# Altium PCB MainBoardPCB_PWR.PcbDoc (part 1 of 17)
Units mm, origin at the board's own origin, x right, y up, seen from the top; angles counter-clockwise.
Board outline 333.63 x 349.38 mm, 16 copper layers (L1, L2 (GND), L3 (Sign), L4 (GND), L5 (Sign), L6 (PWR/GND), L7(PWR/GND), L8 (PWR/GND), L9 (PWR/GND), L10 (PWR/GND), L11 (PWR/GND), L12 (Sign), L13 (GND), L14 (Sign), L15 (GND), L16), stack 2.503 mm thick; 2187 components, 1615 nets, 7987 pads, 1695 vias.
Unrouted connection lines stored in the file: 4757.
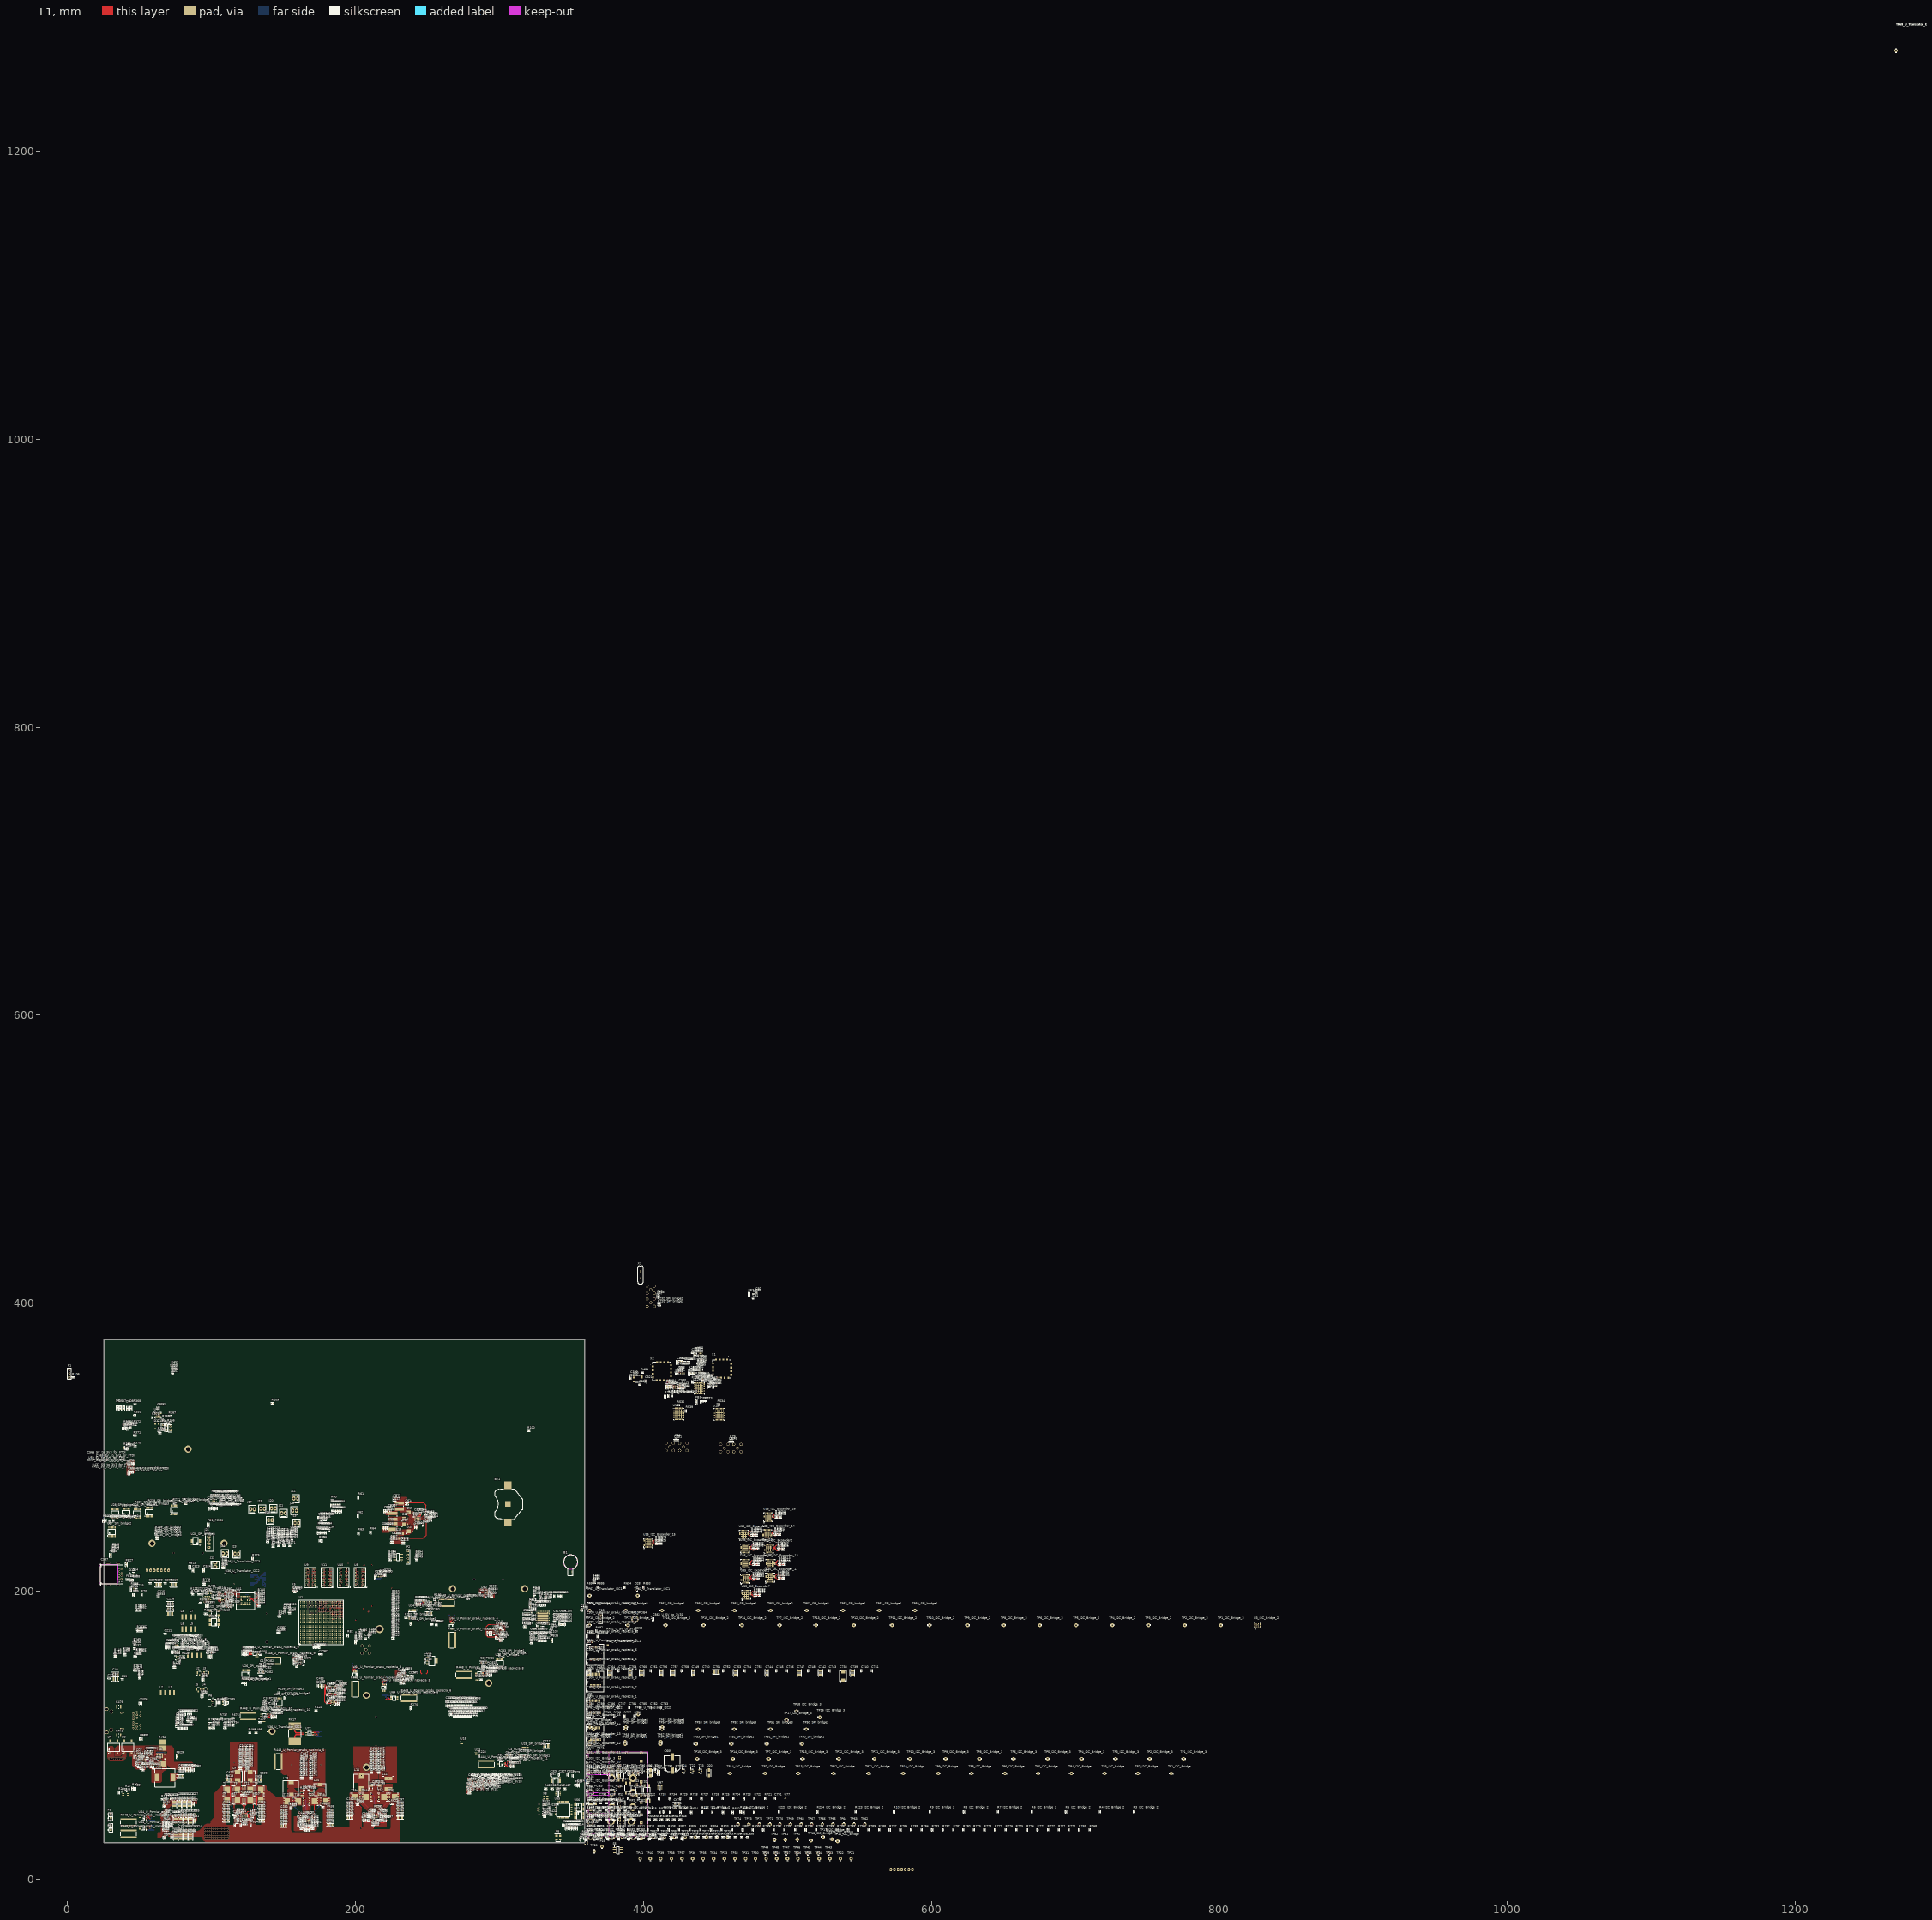
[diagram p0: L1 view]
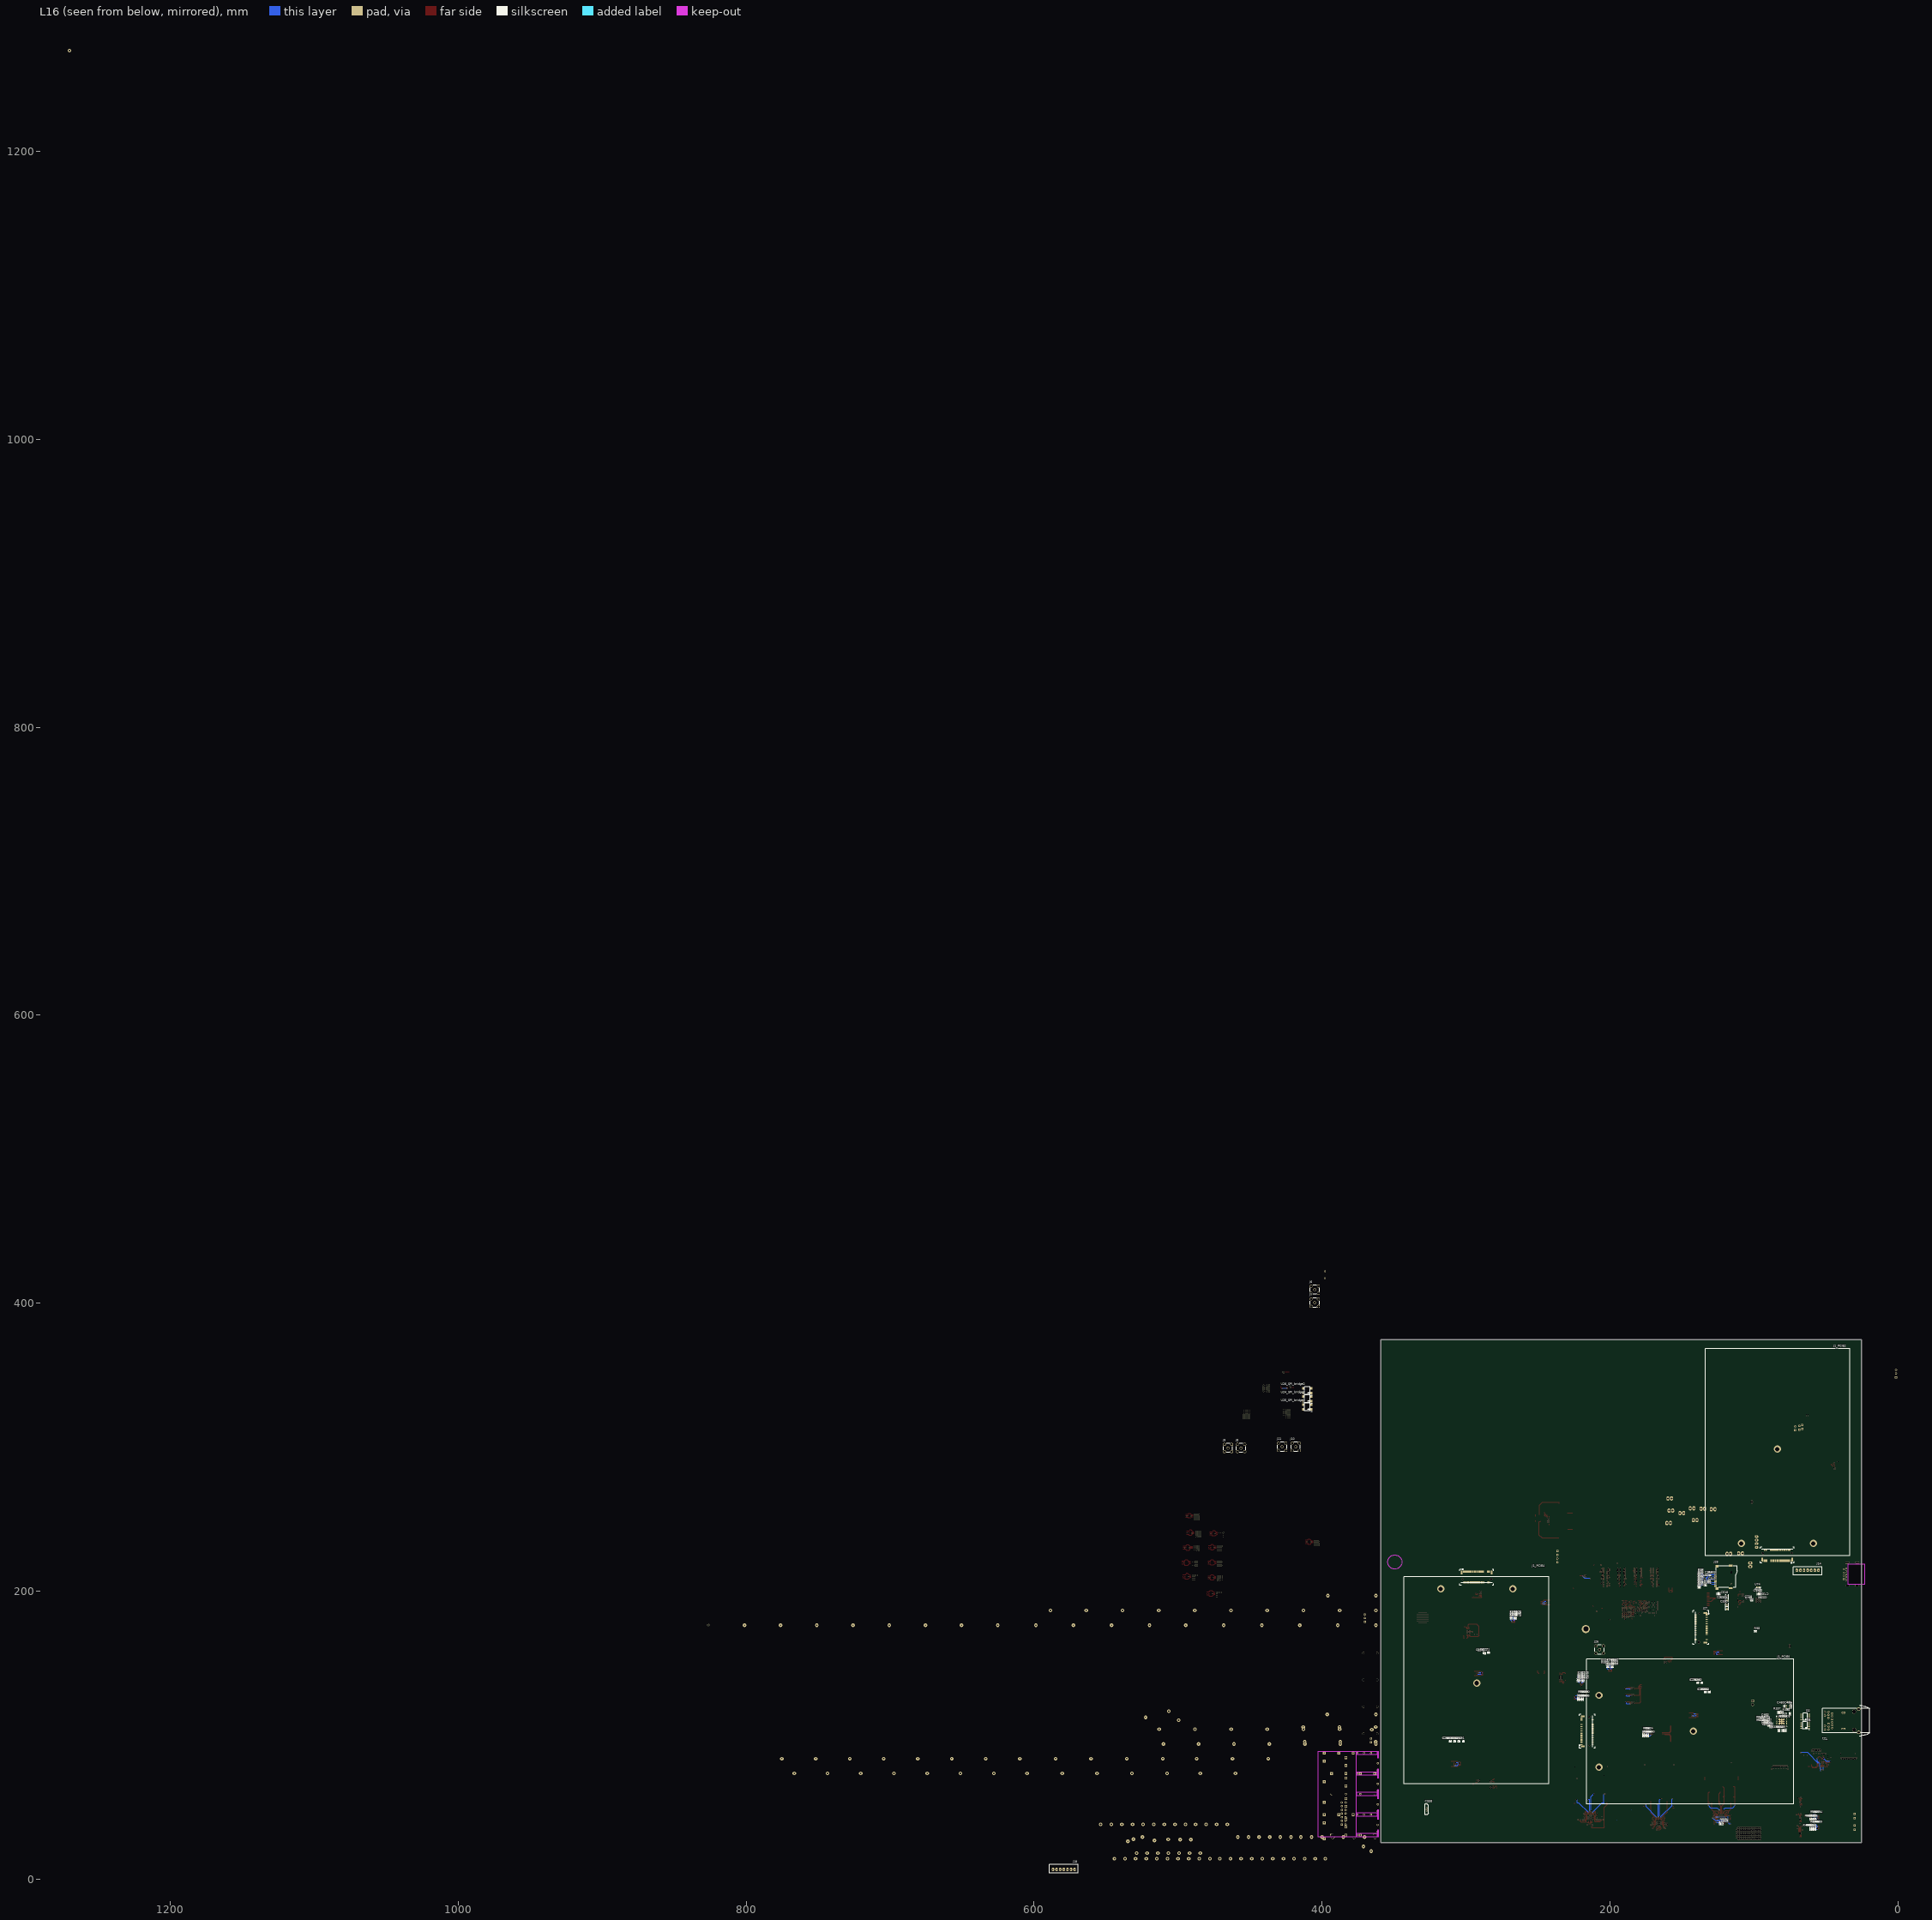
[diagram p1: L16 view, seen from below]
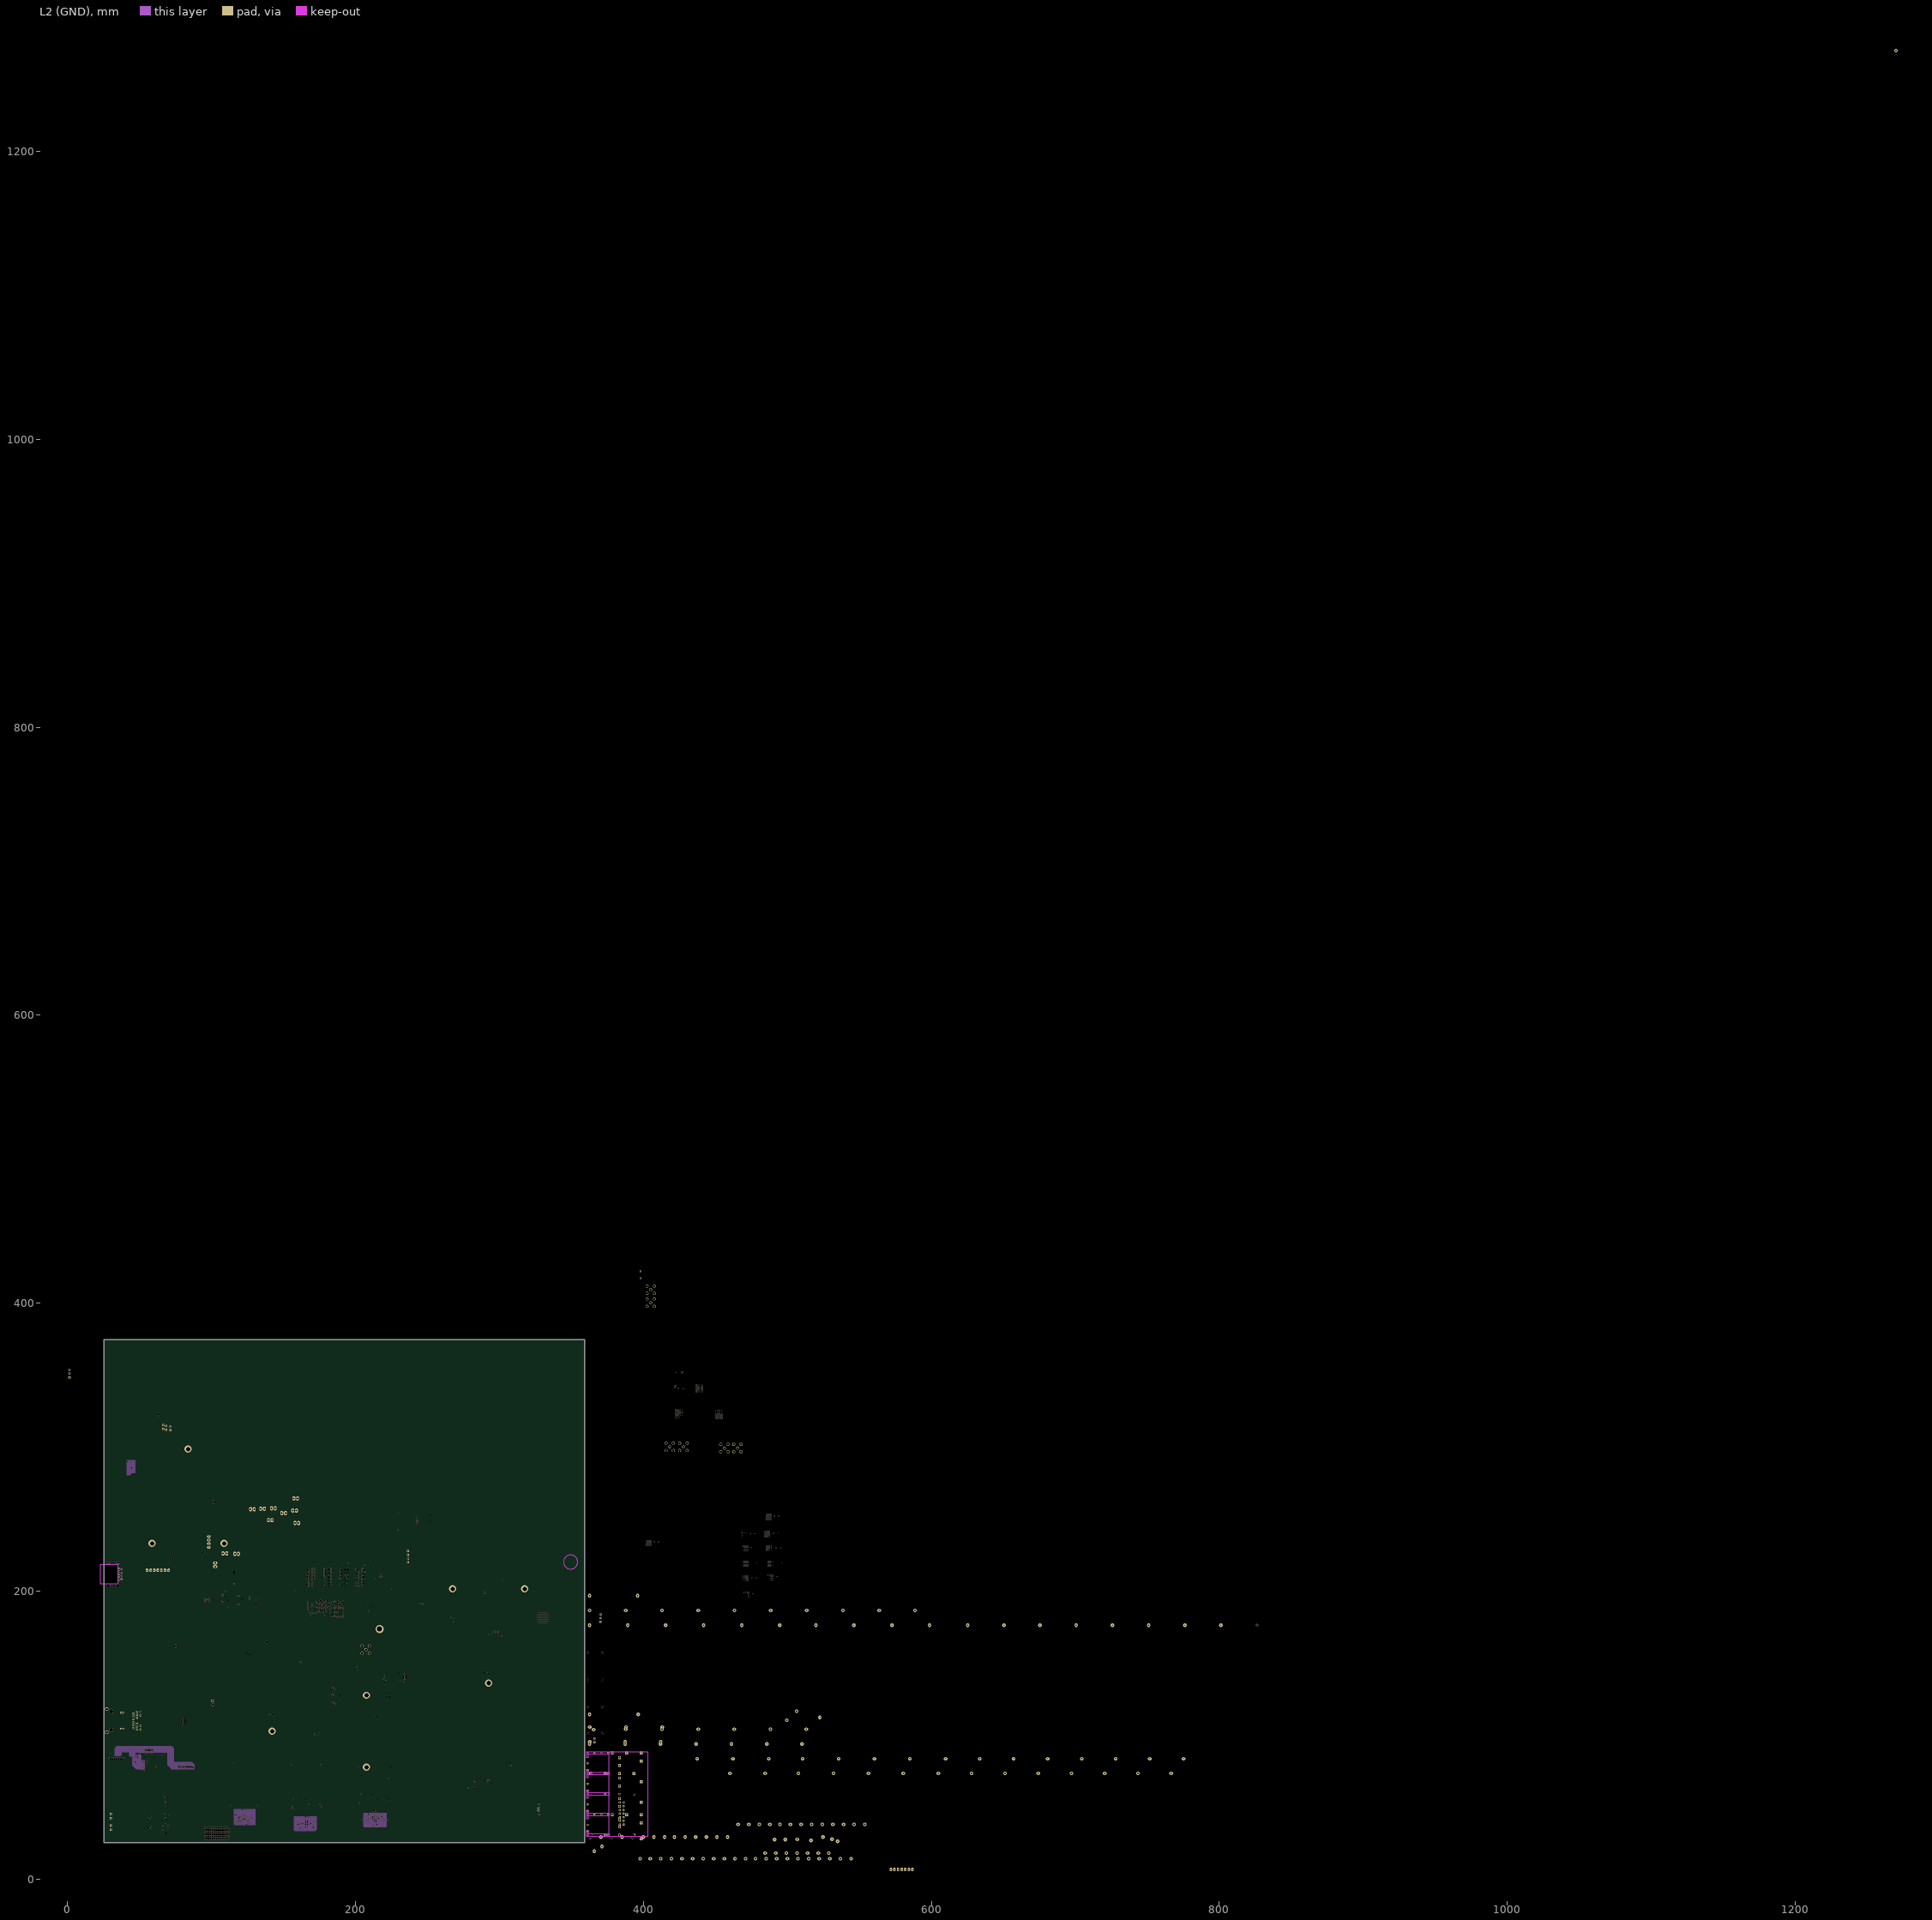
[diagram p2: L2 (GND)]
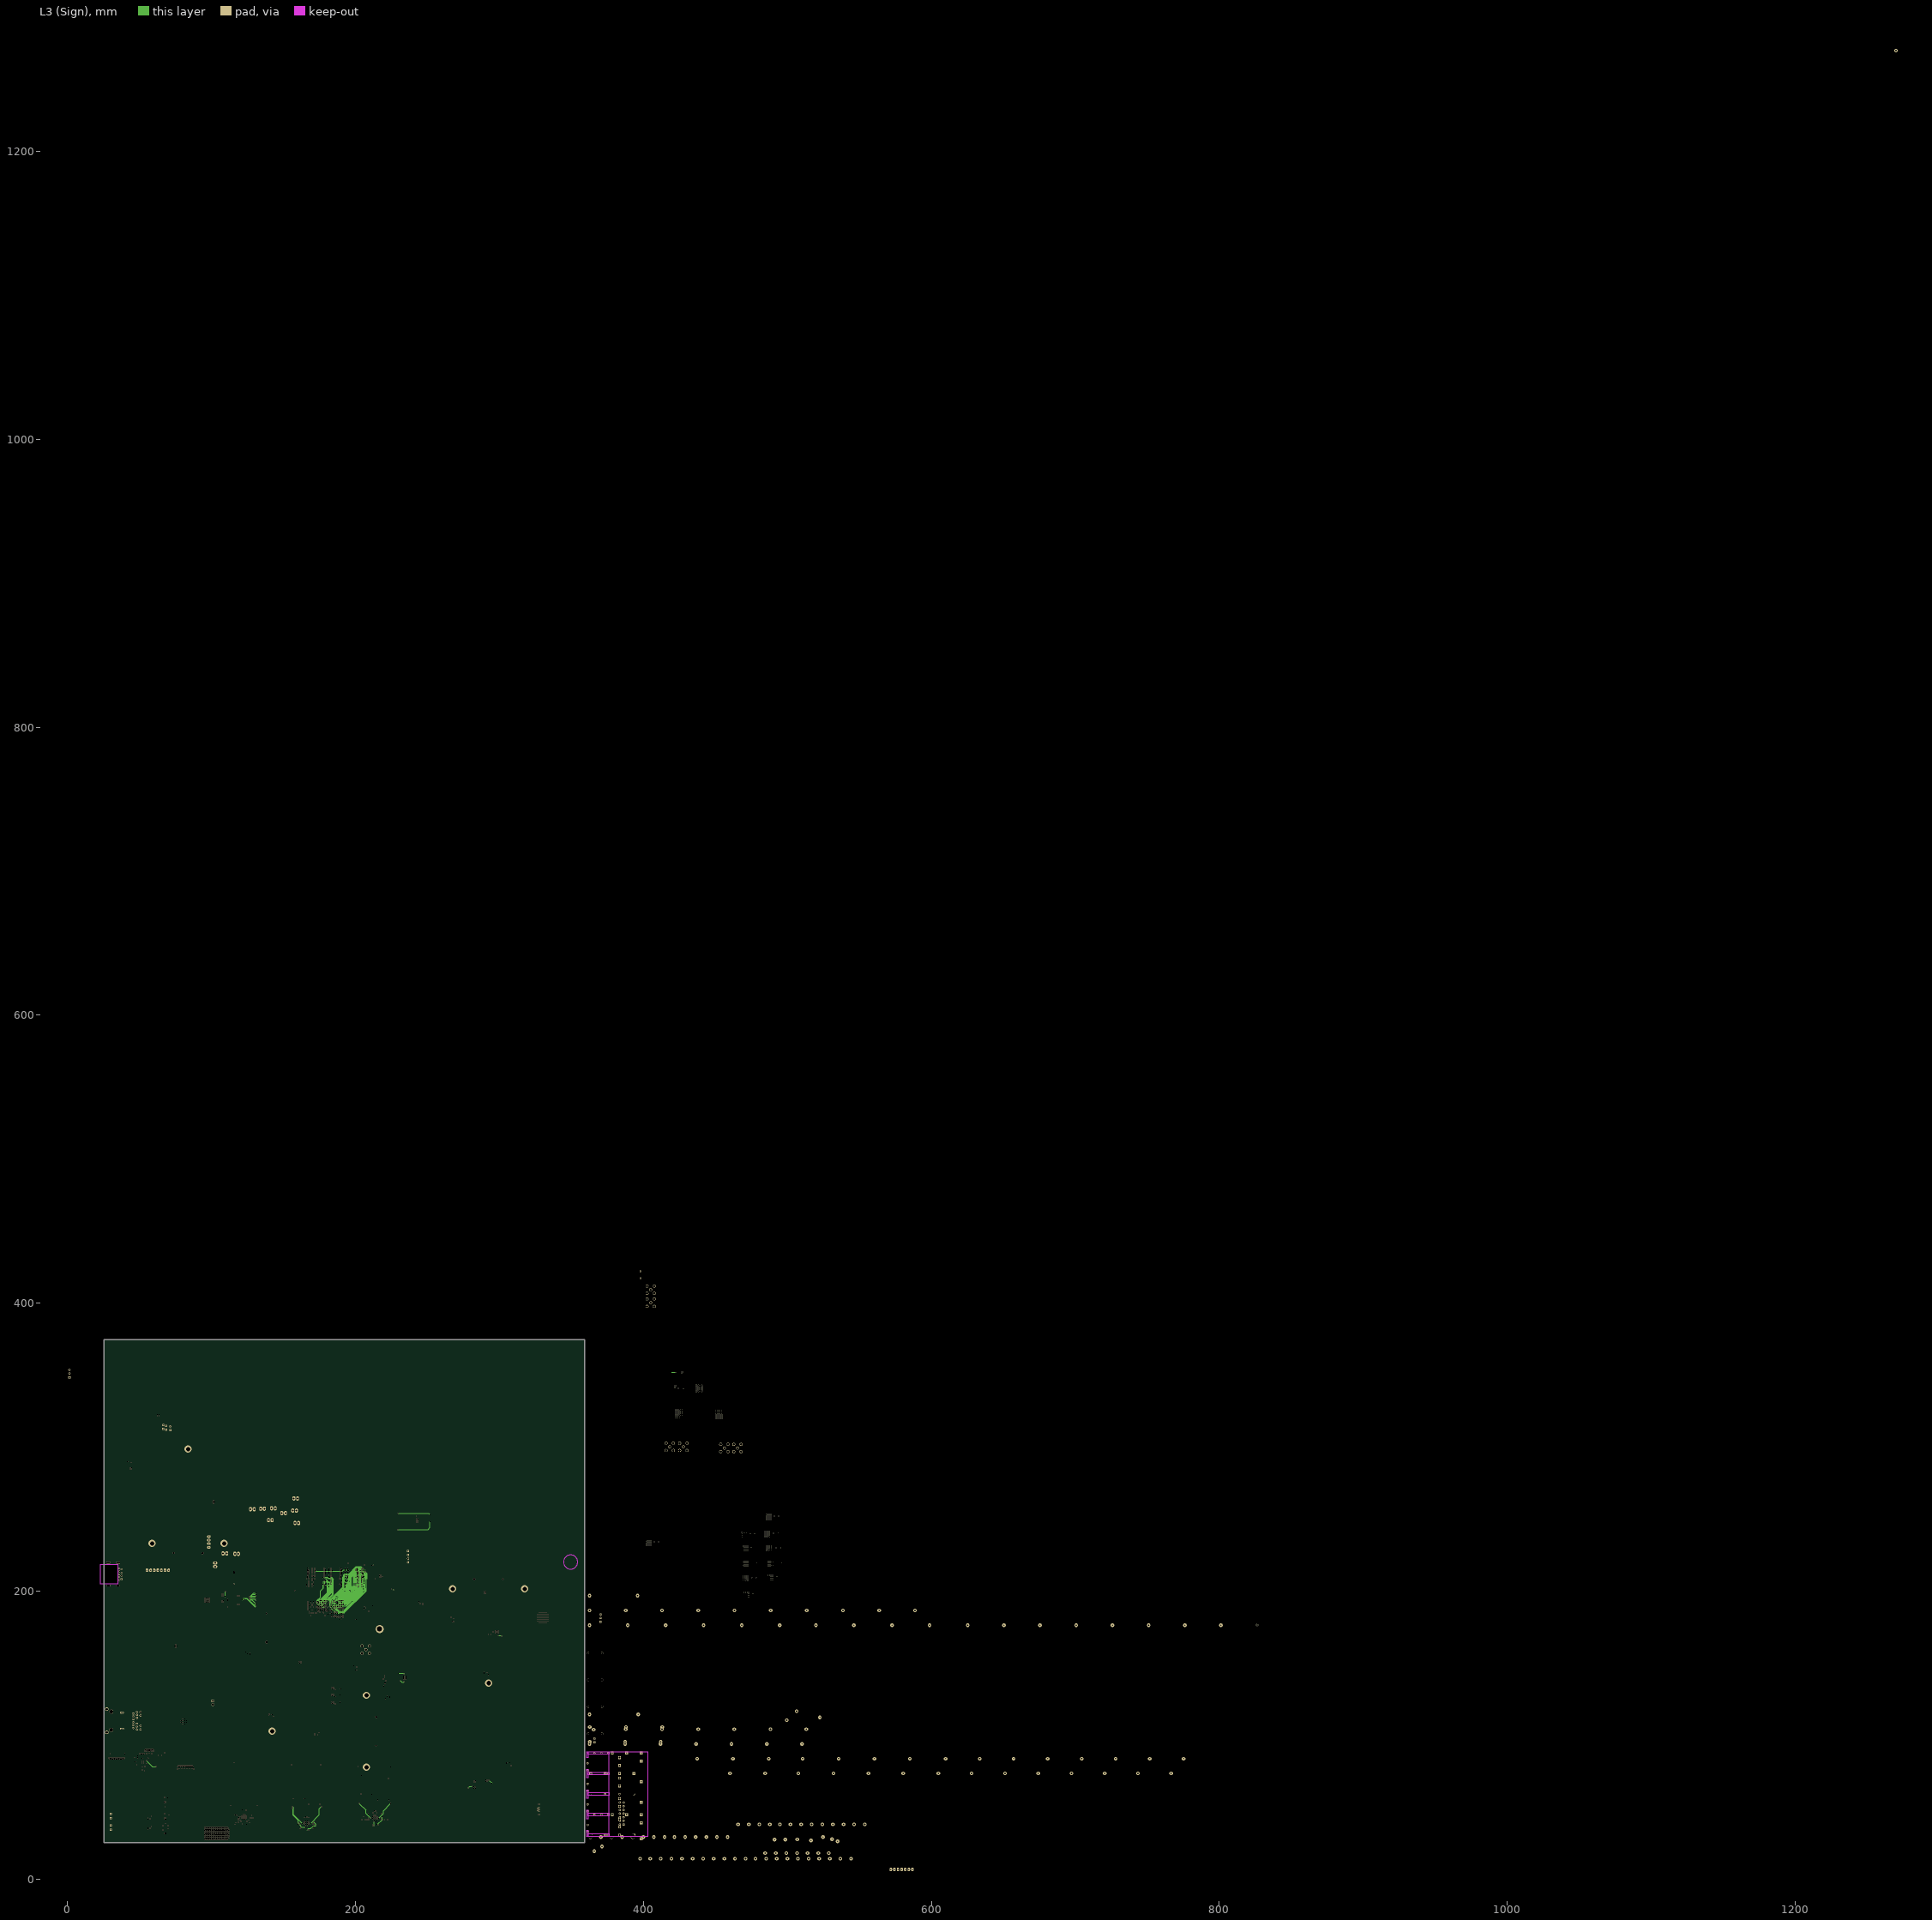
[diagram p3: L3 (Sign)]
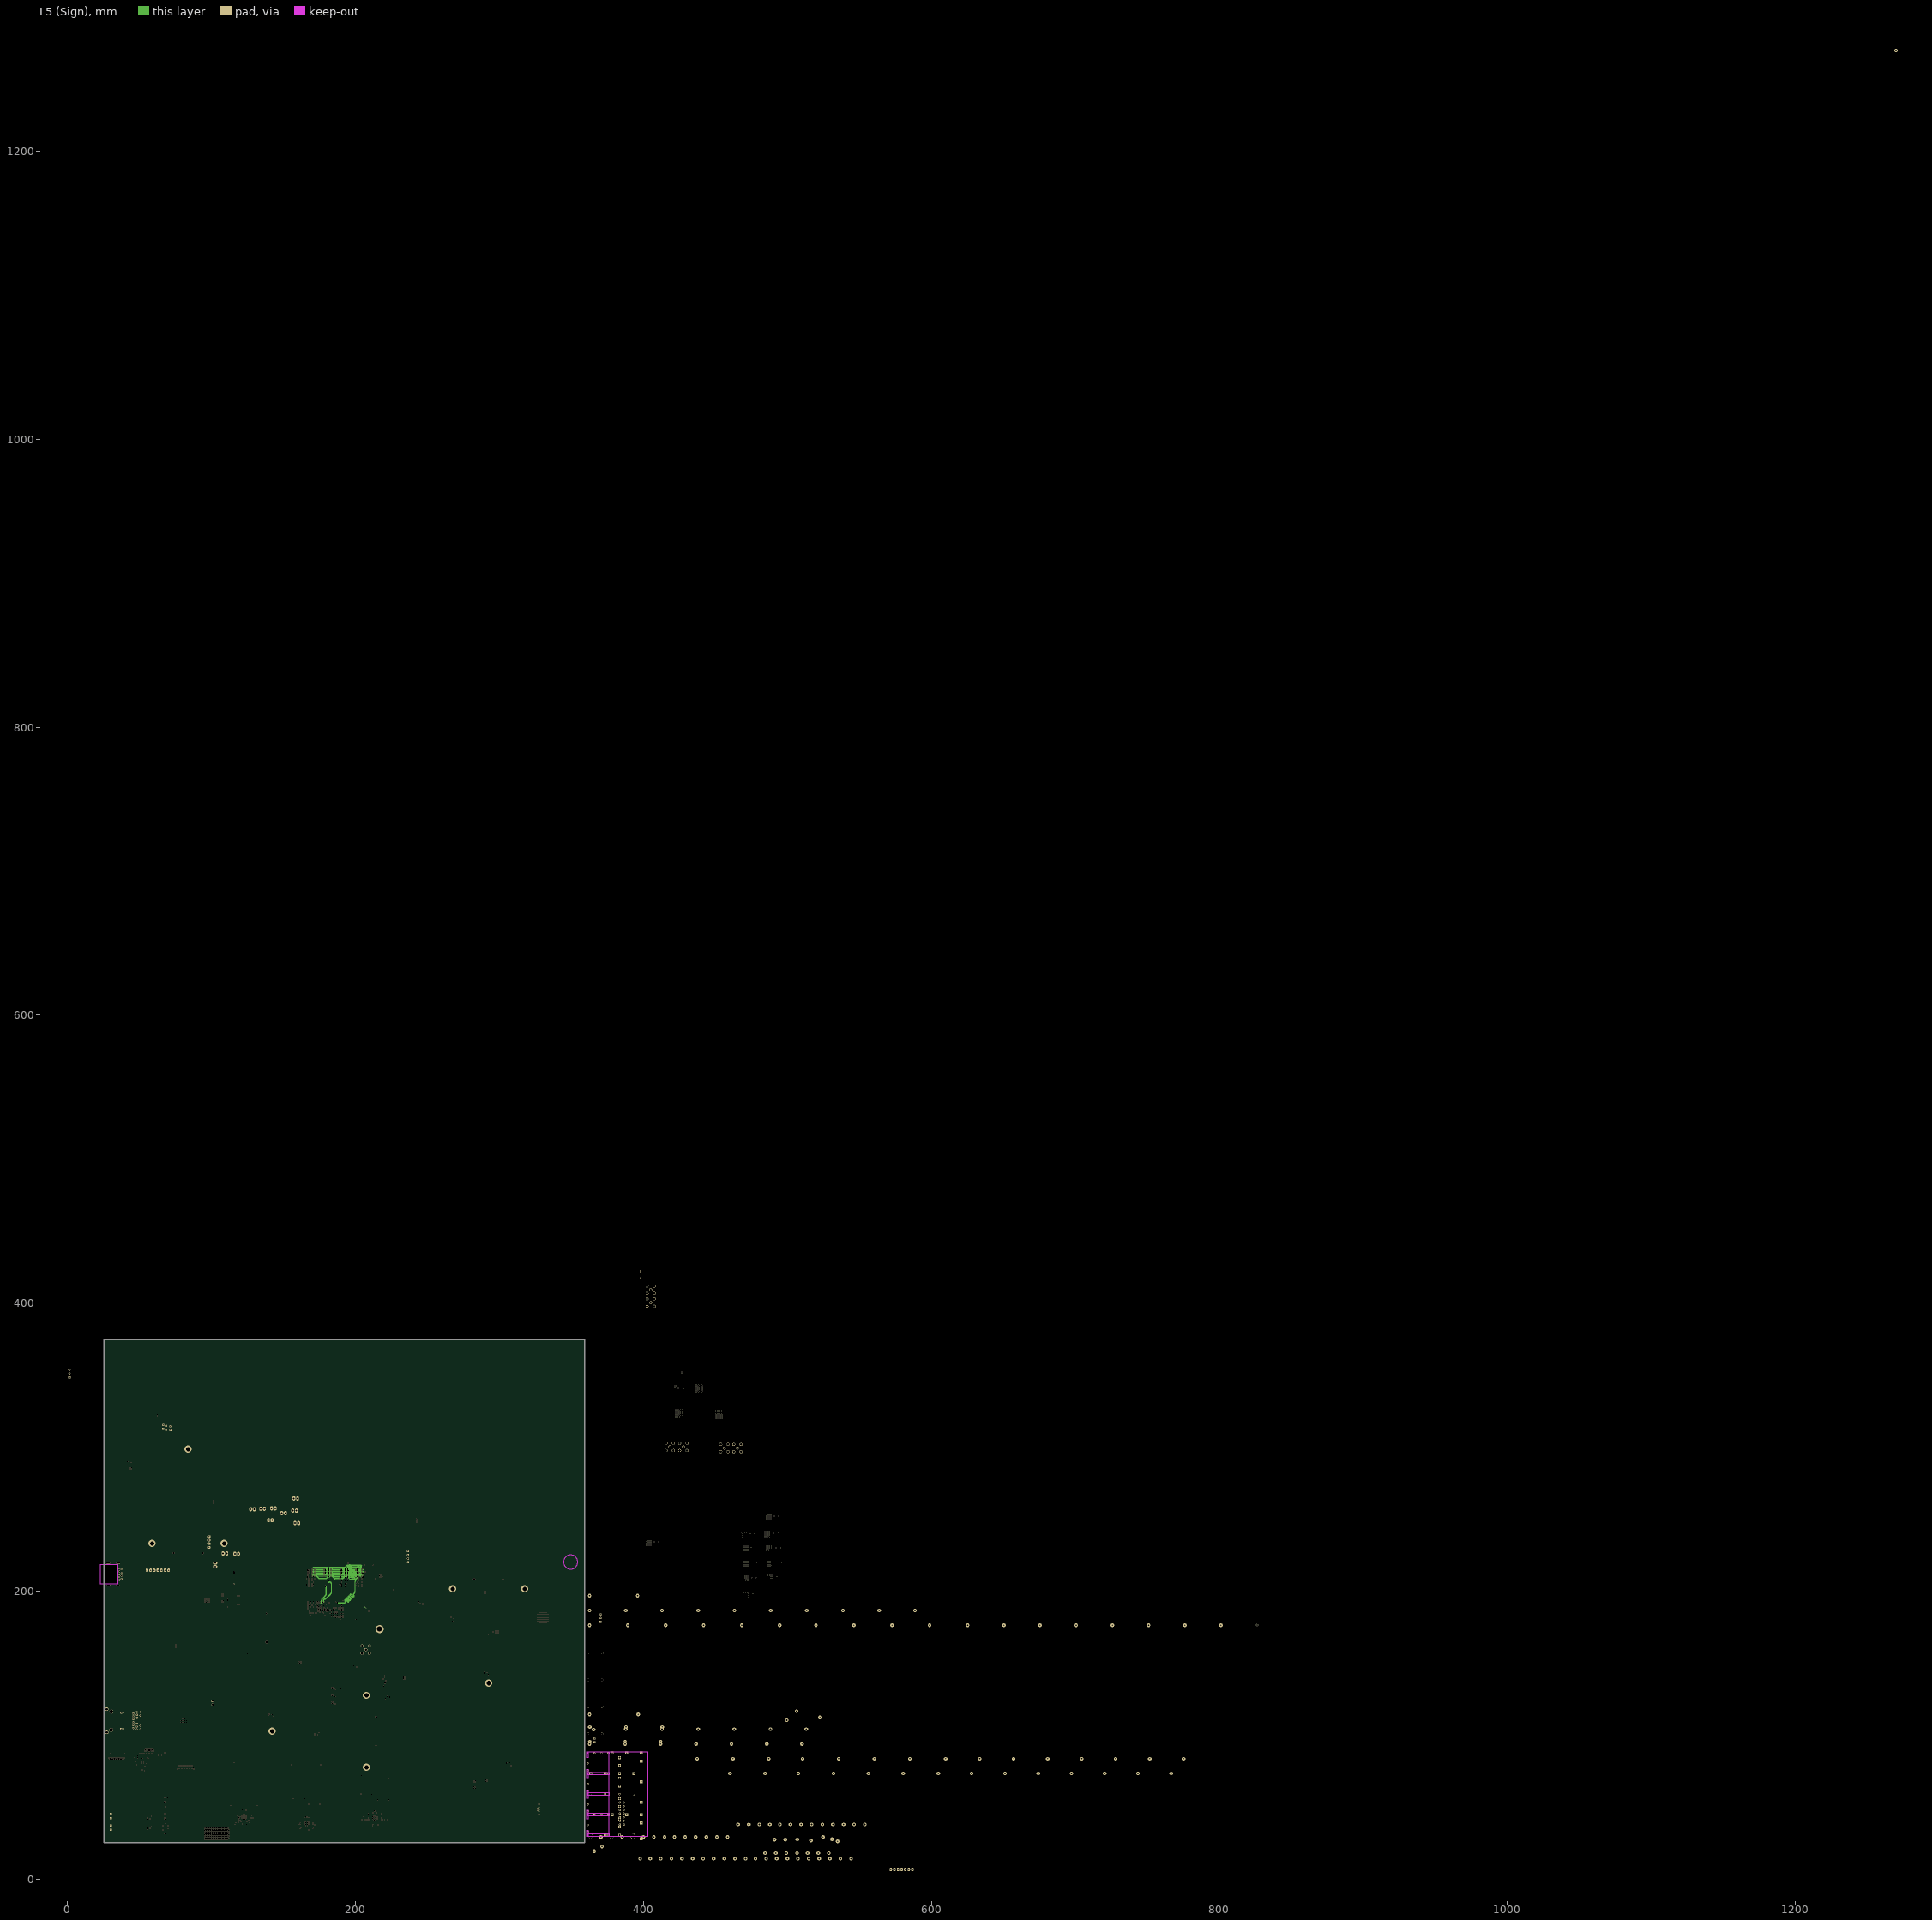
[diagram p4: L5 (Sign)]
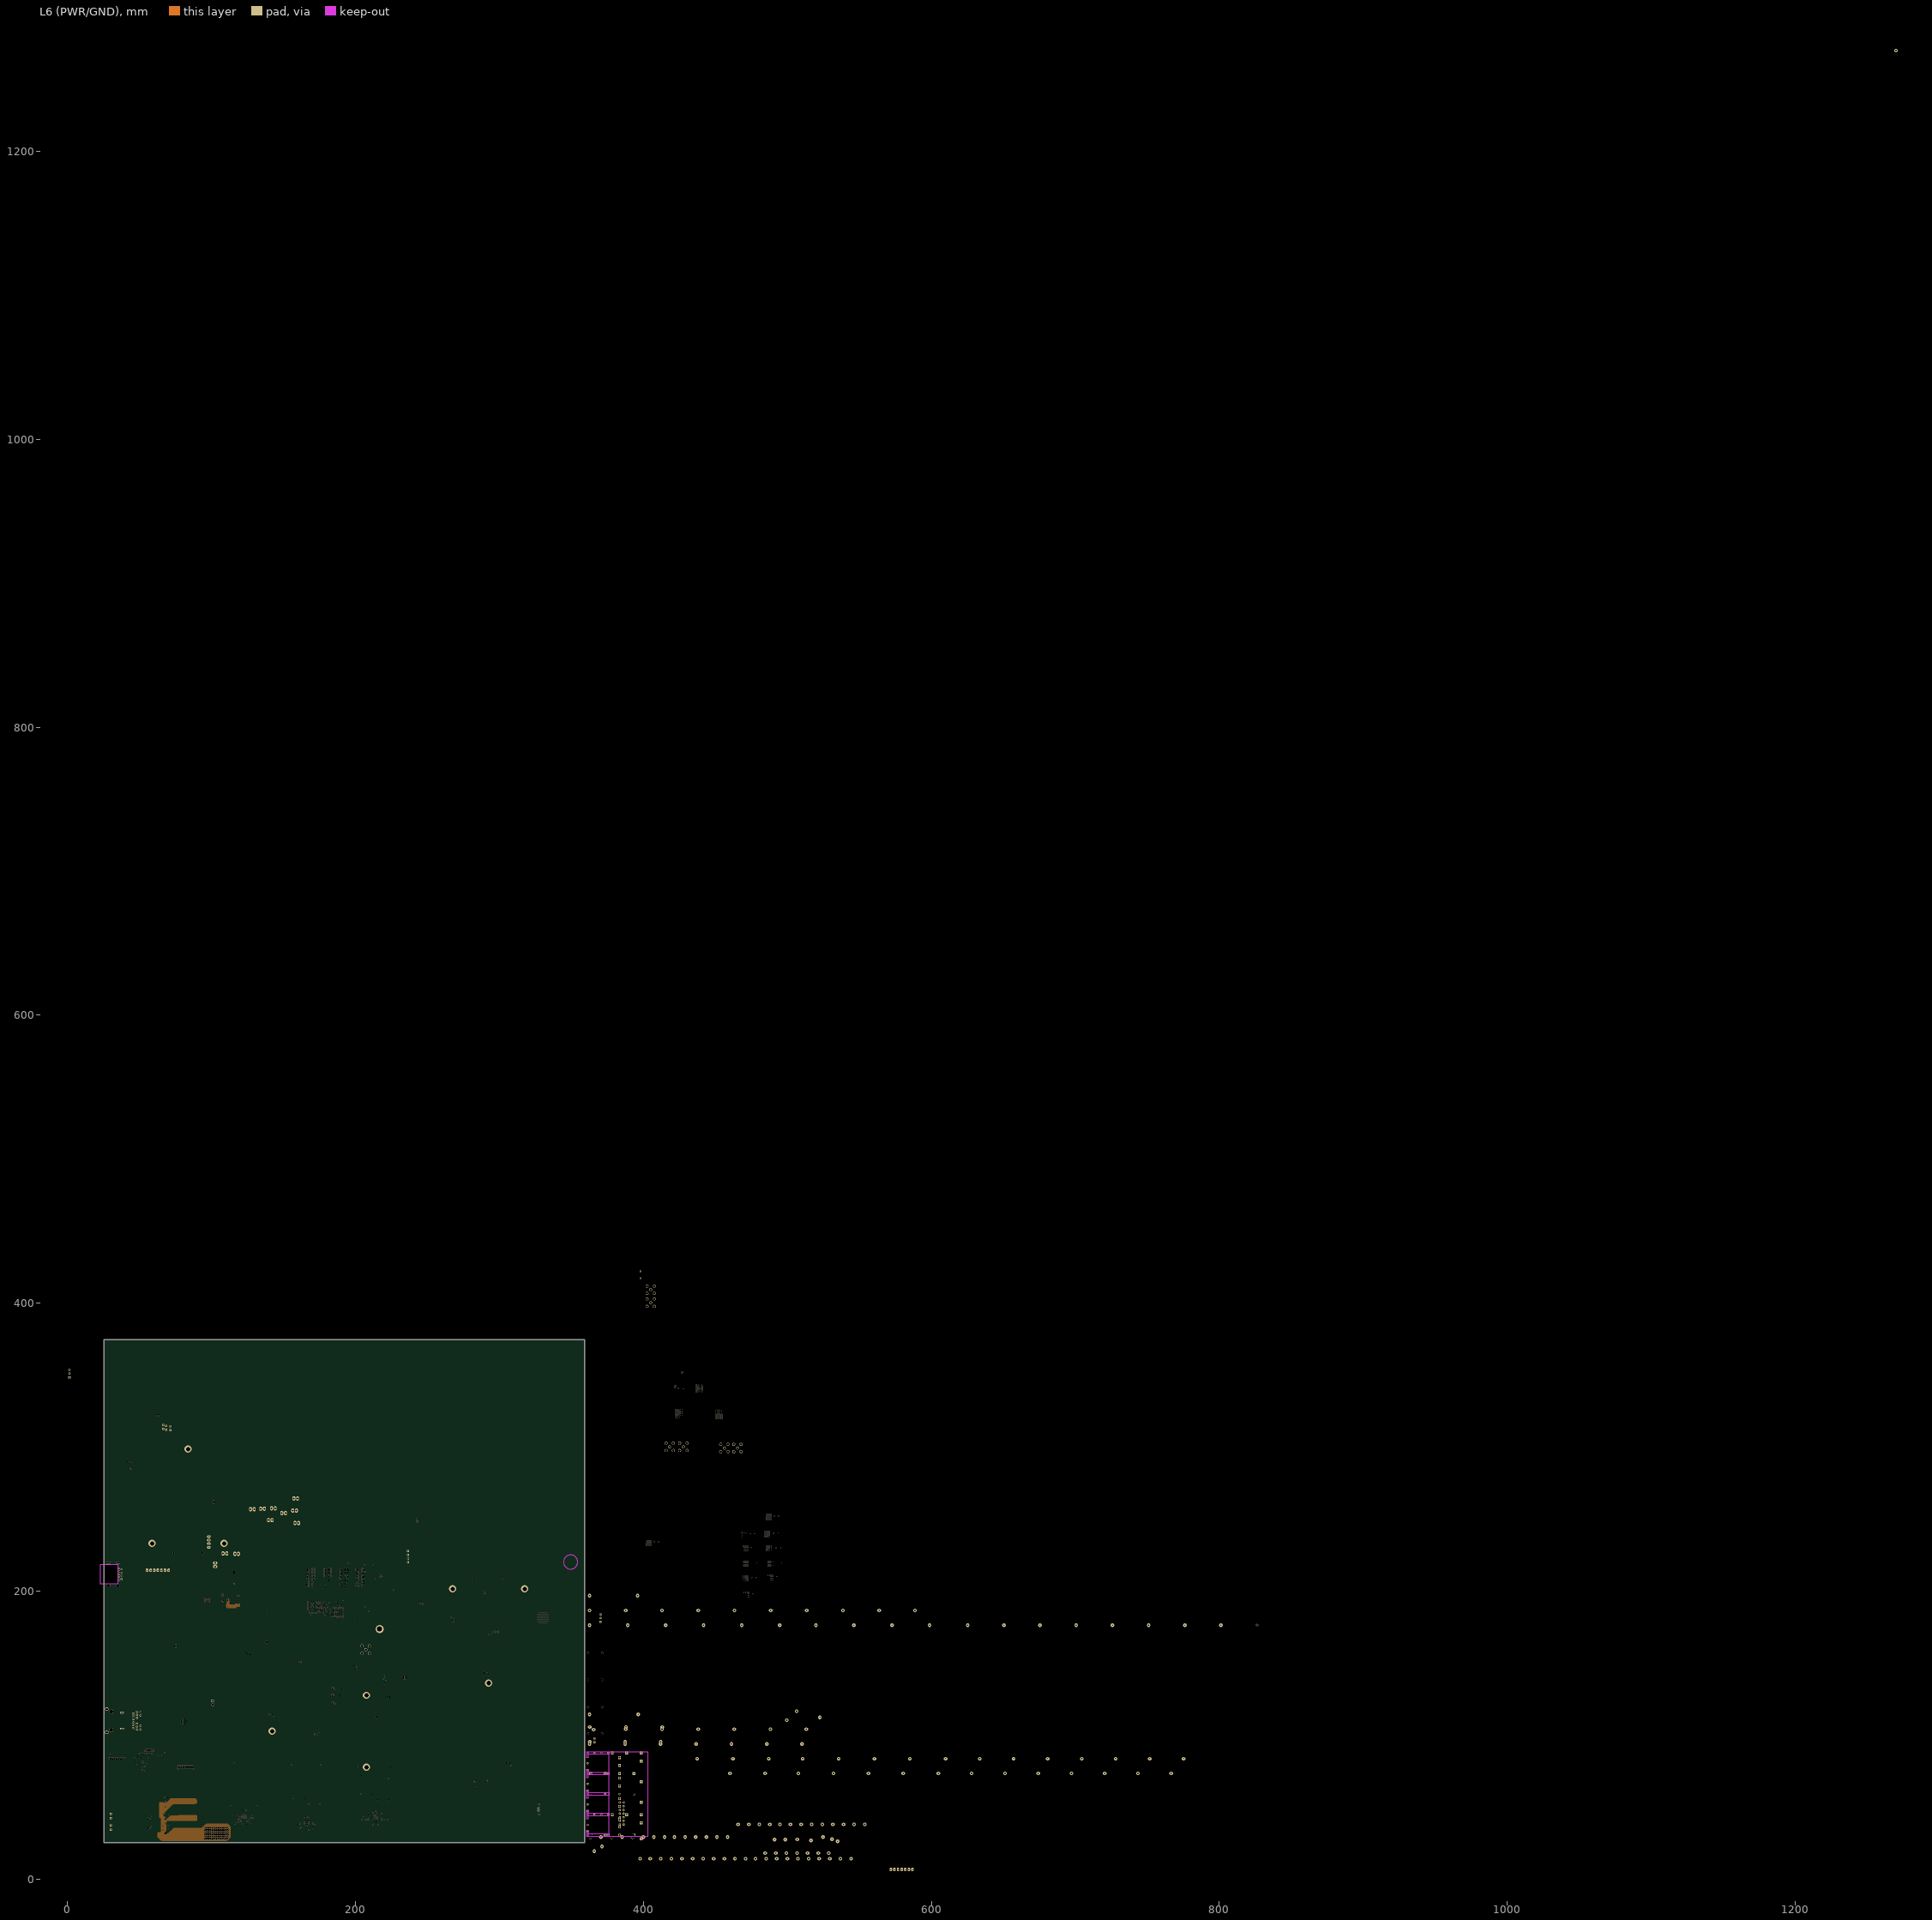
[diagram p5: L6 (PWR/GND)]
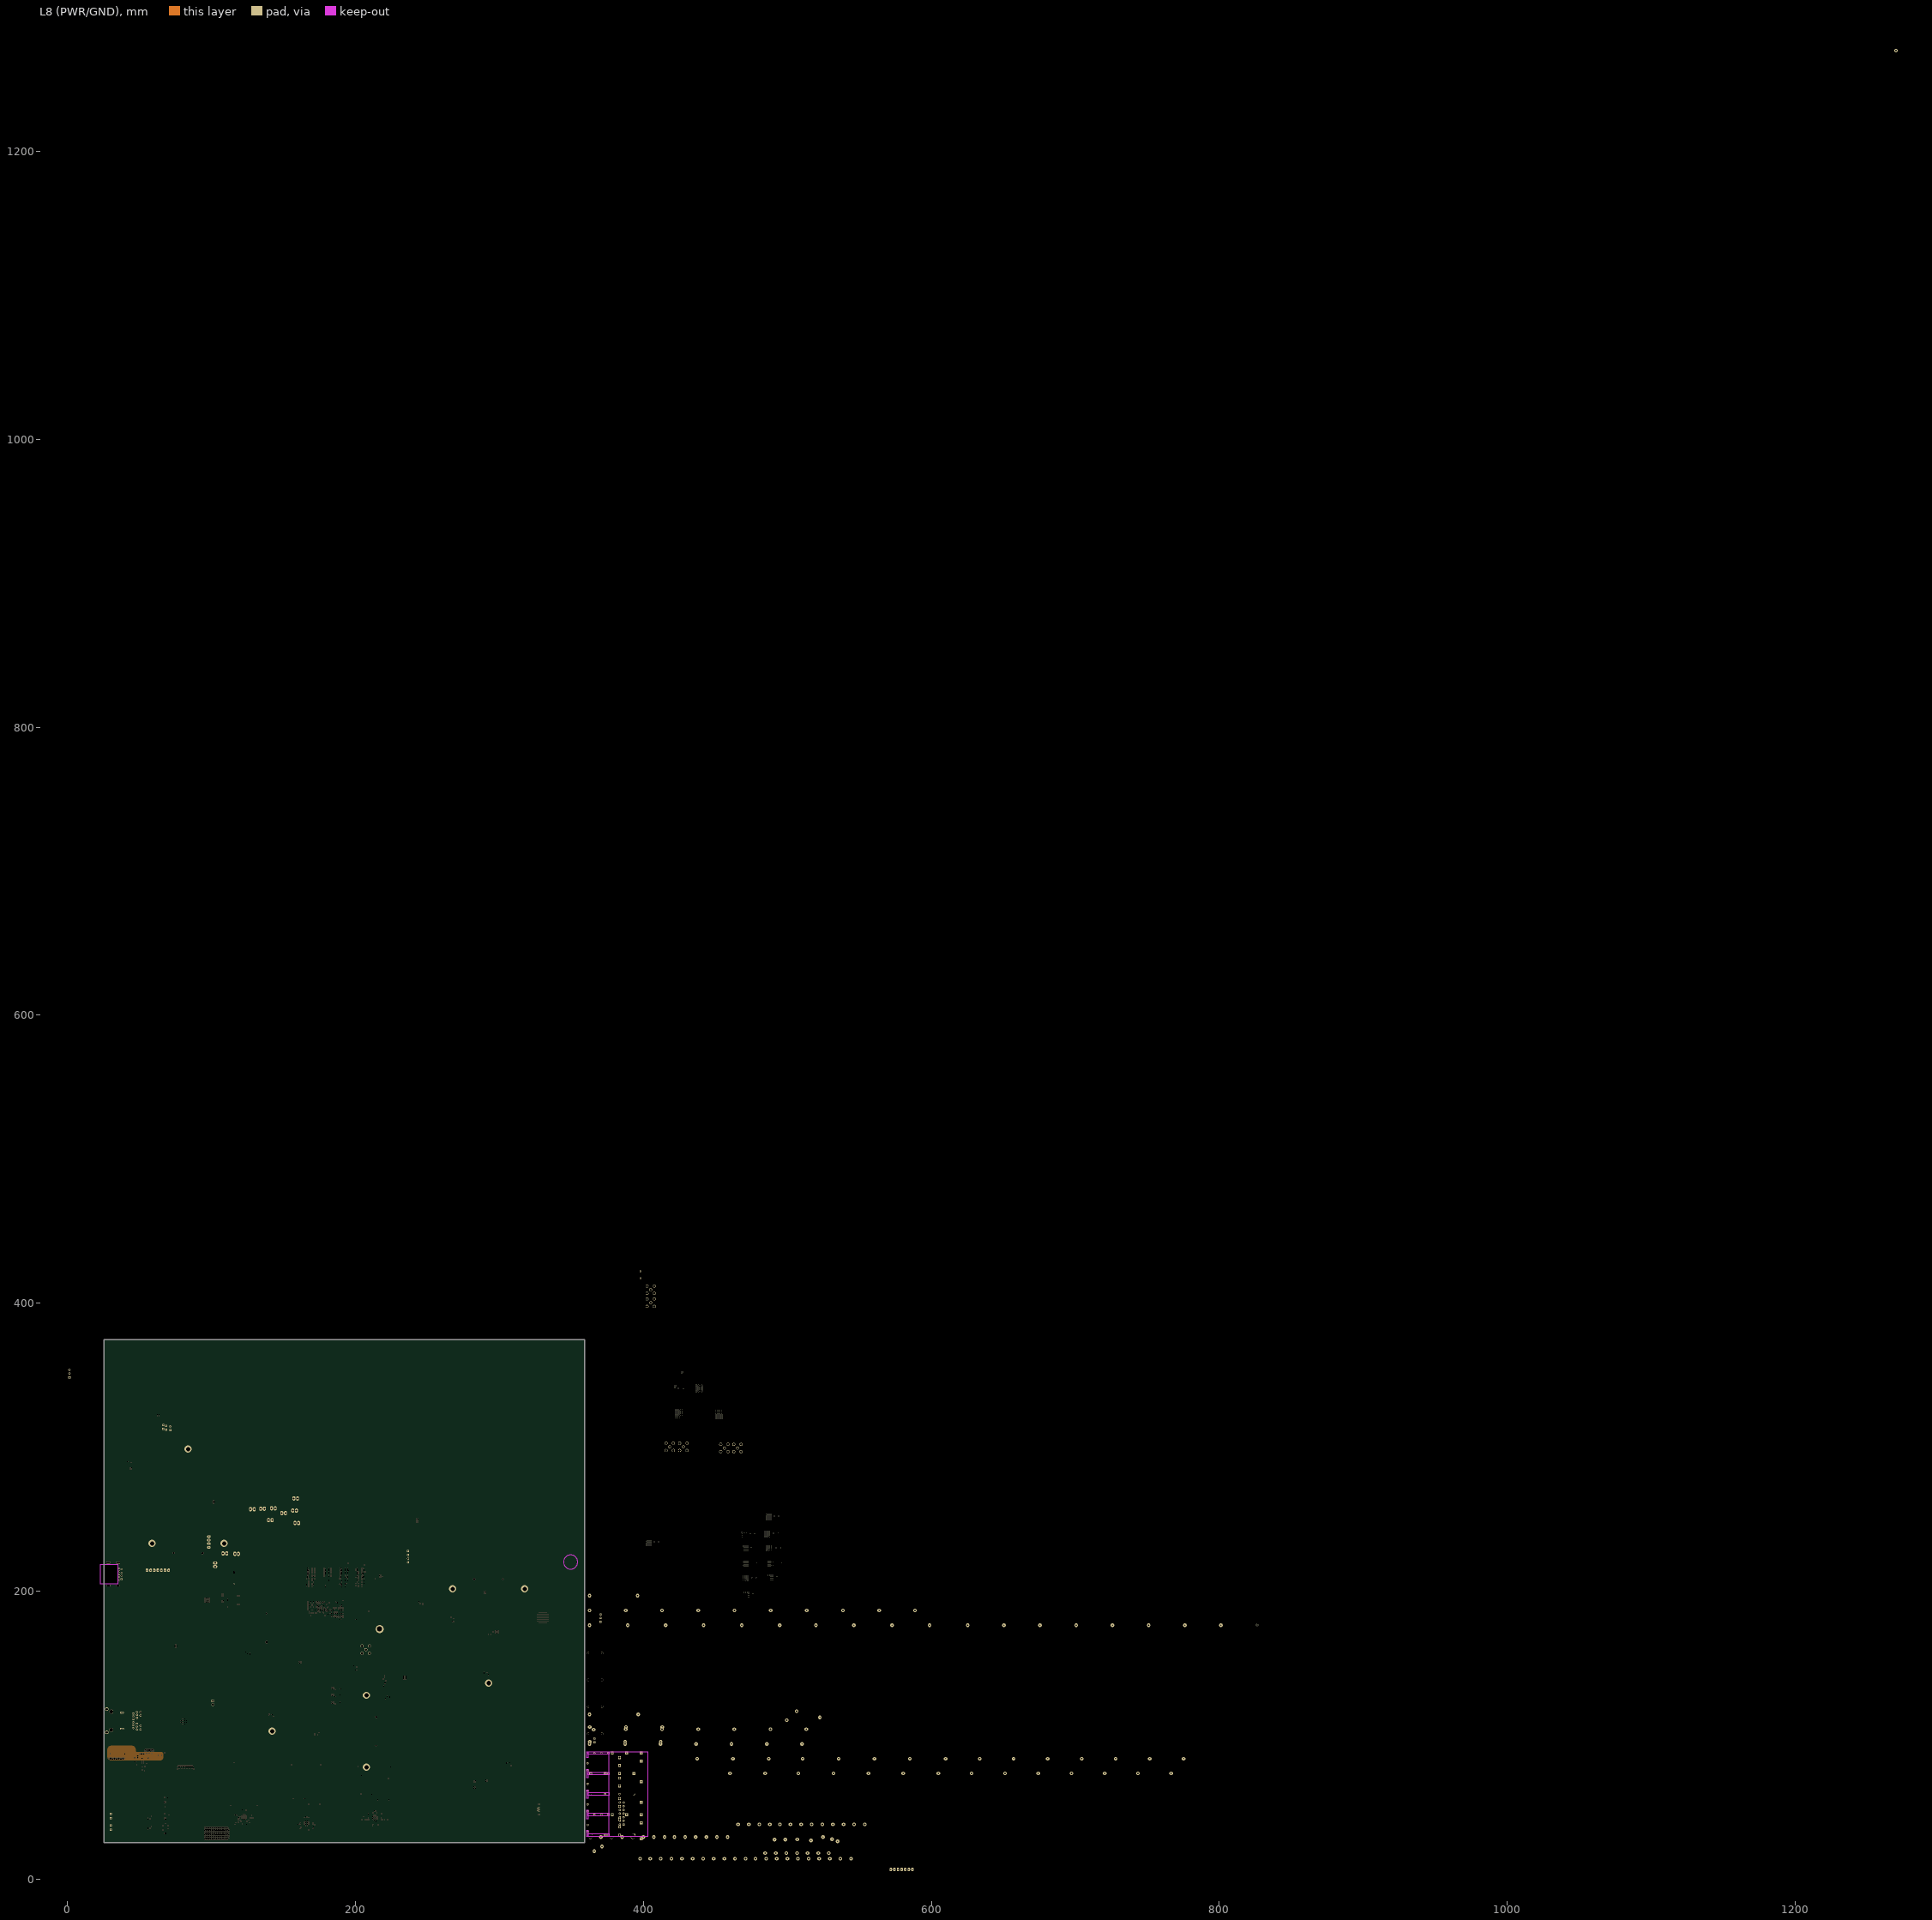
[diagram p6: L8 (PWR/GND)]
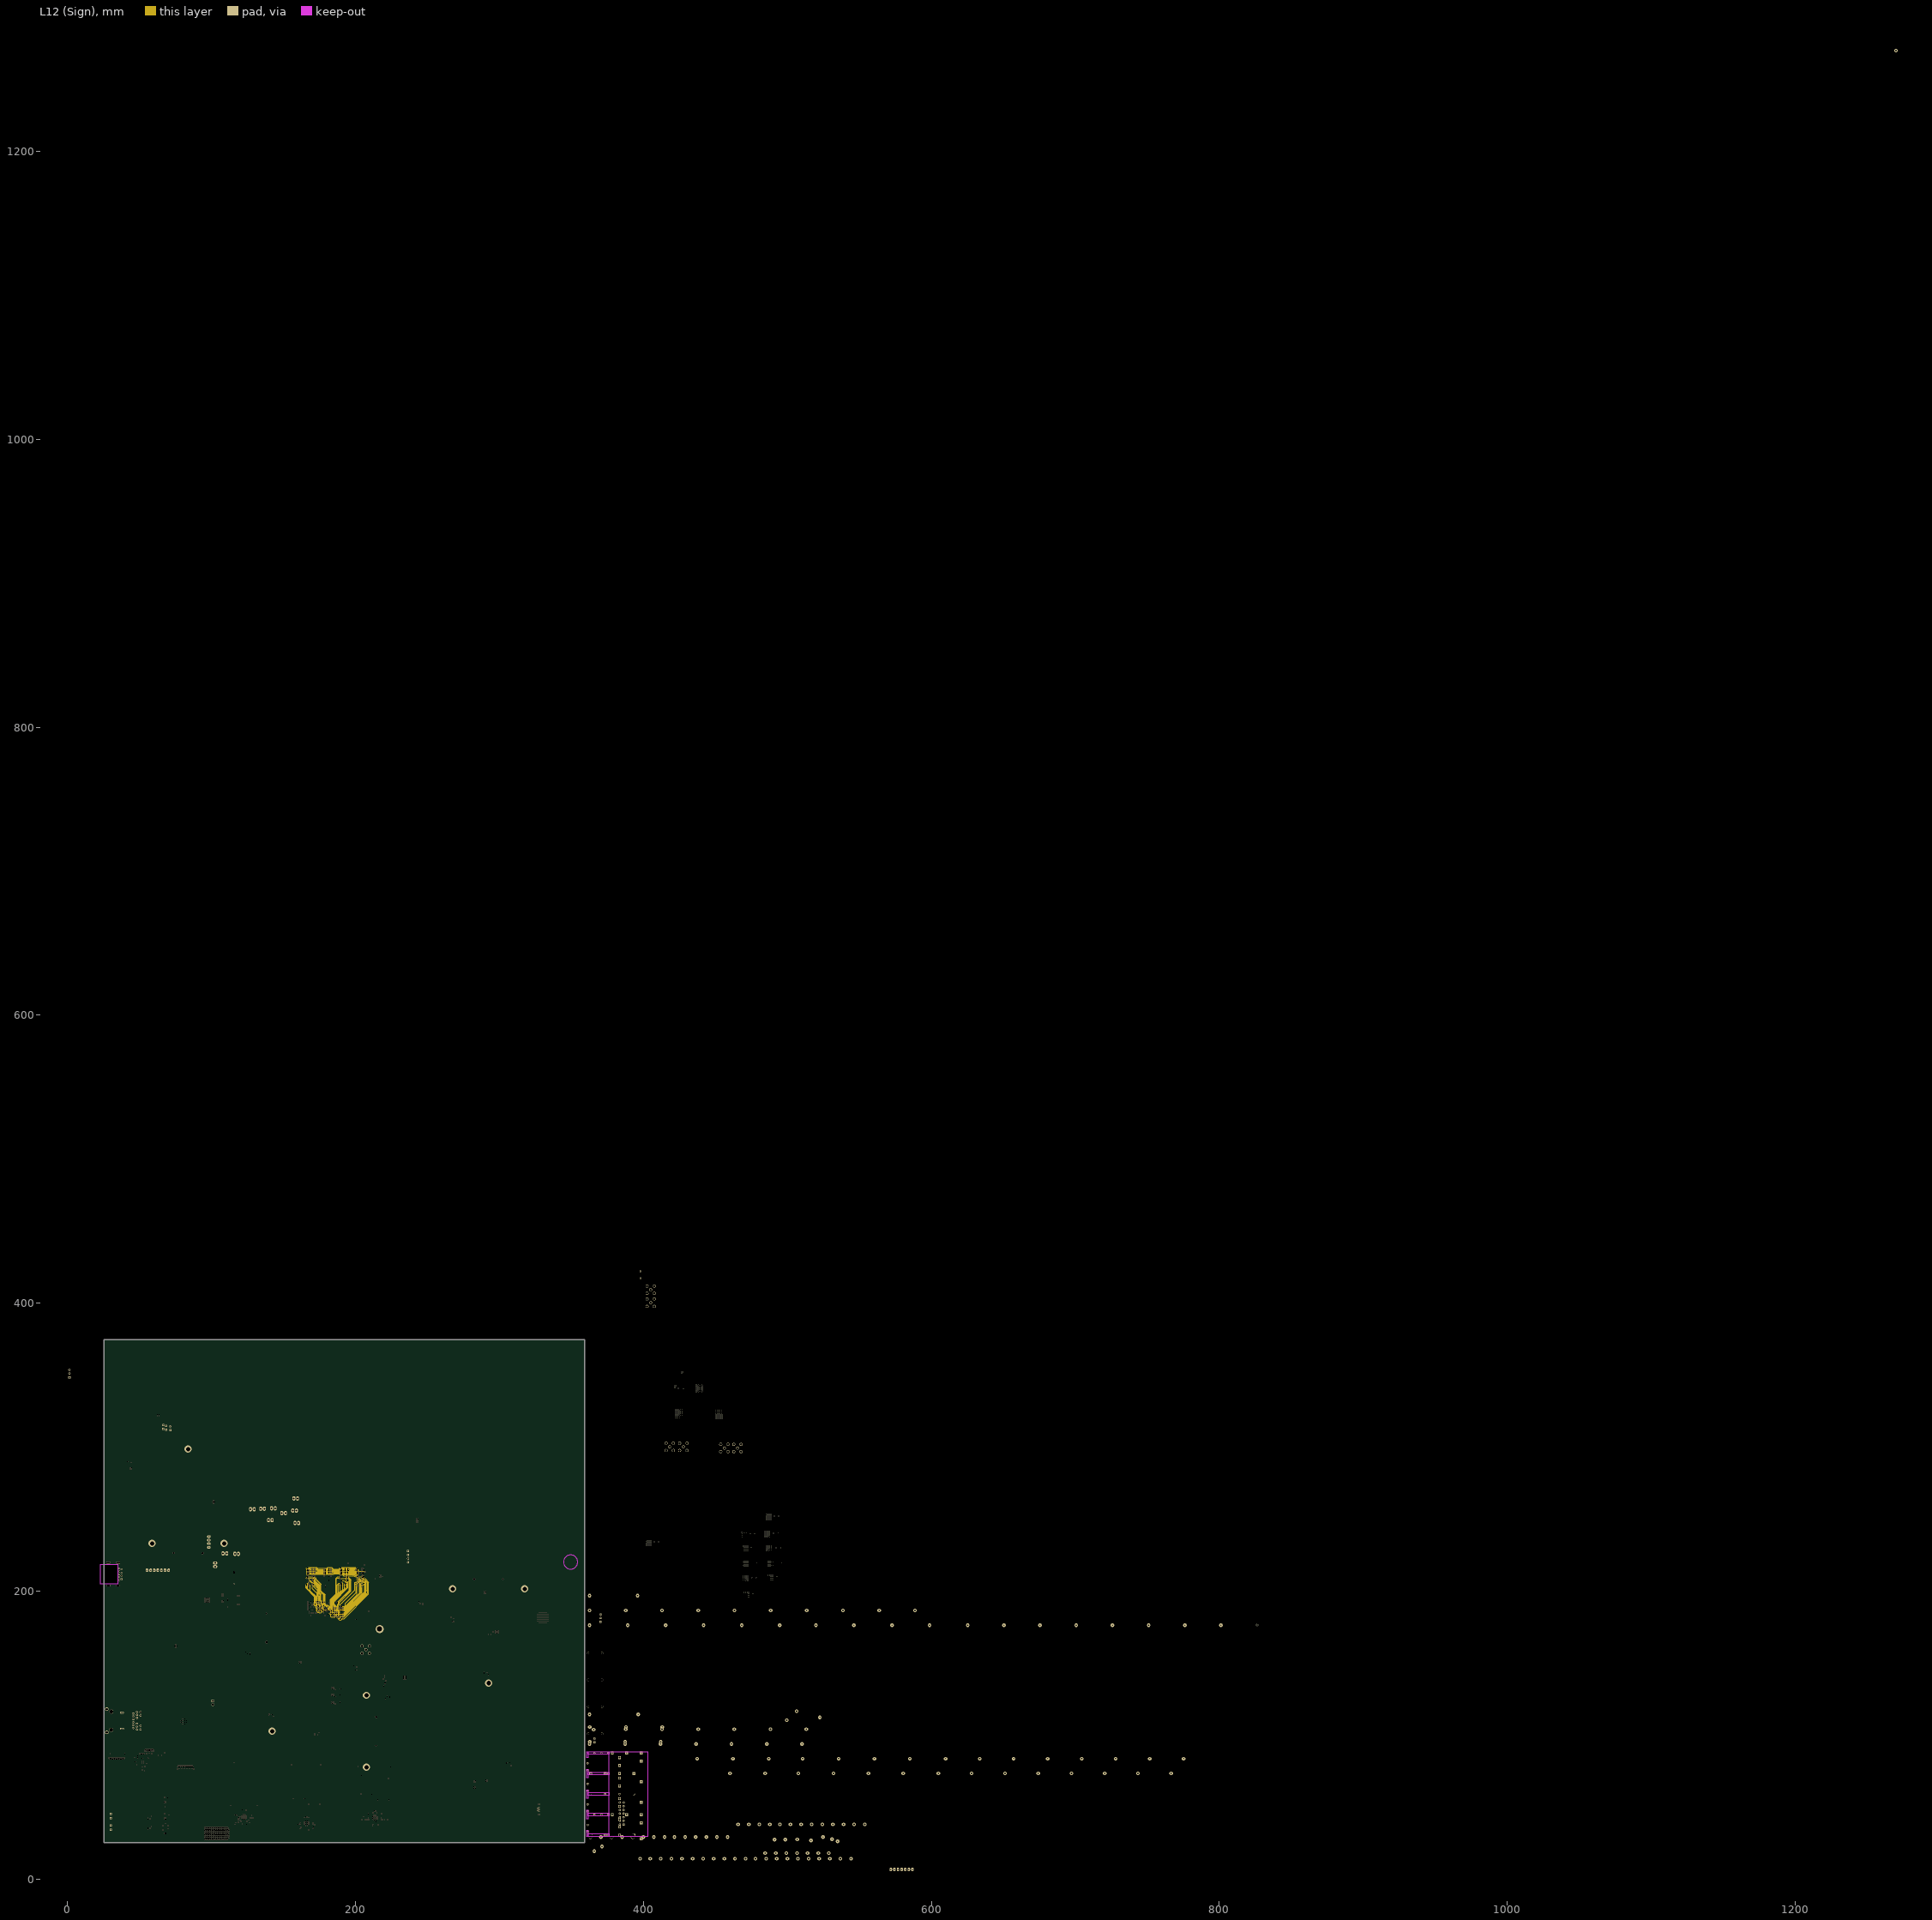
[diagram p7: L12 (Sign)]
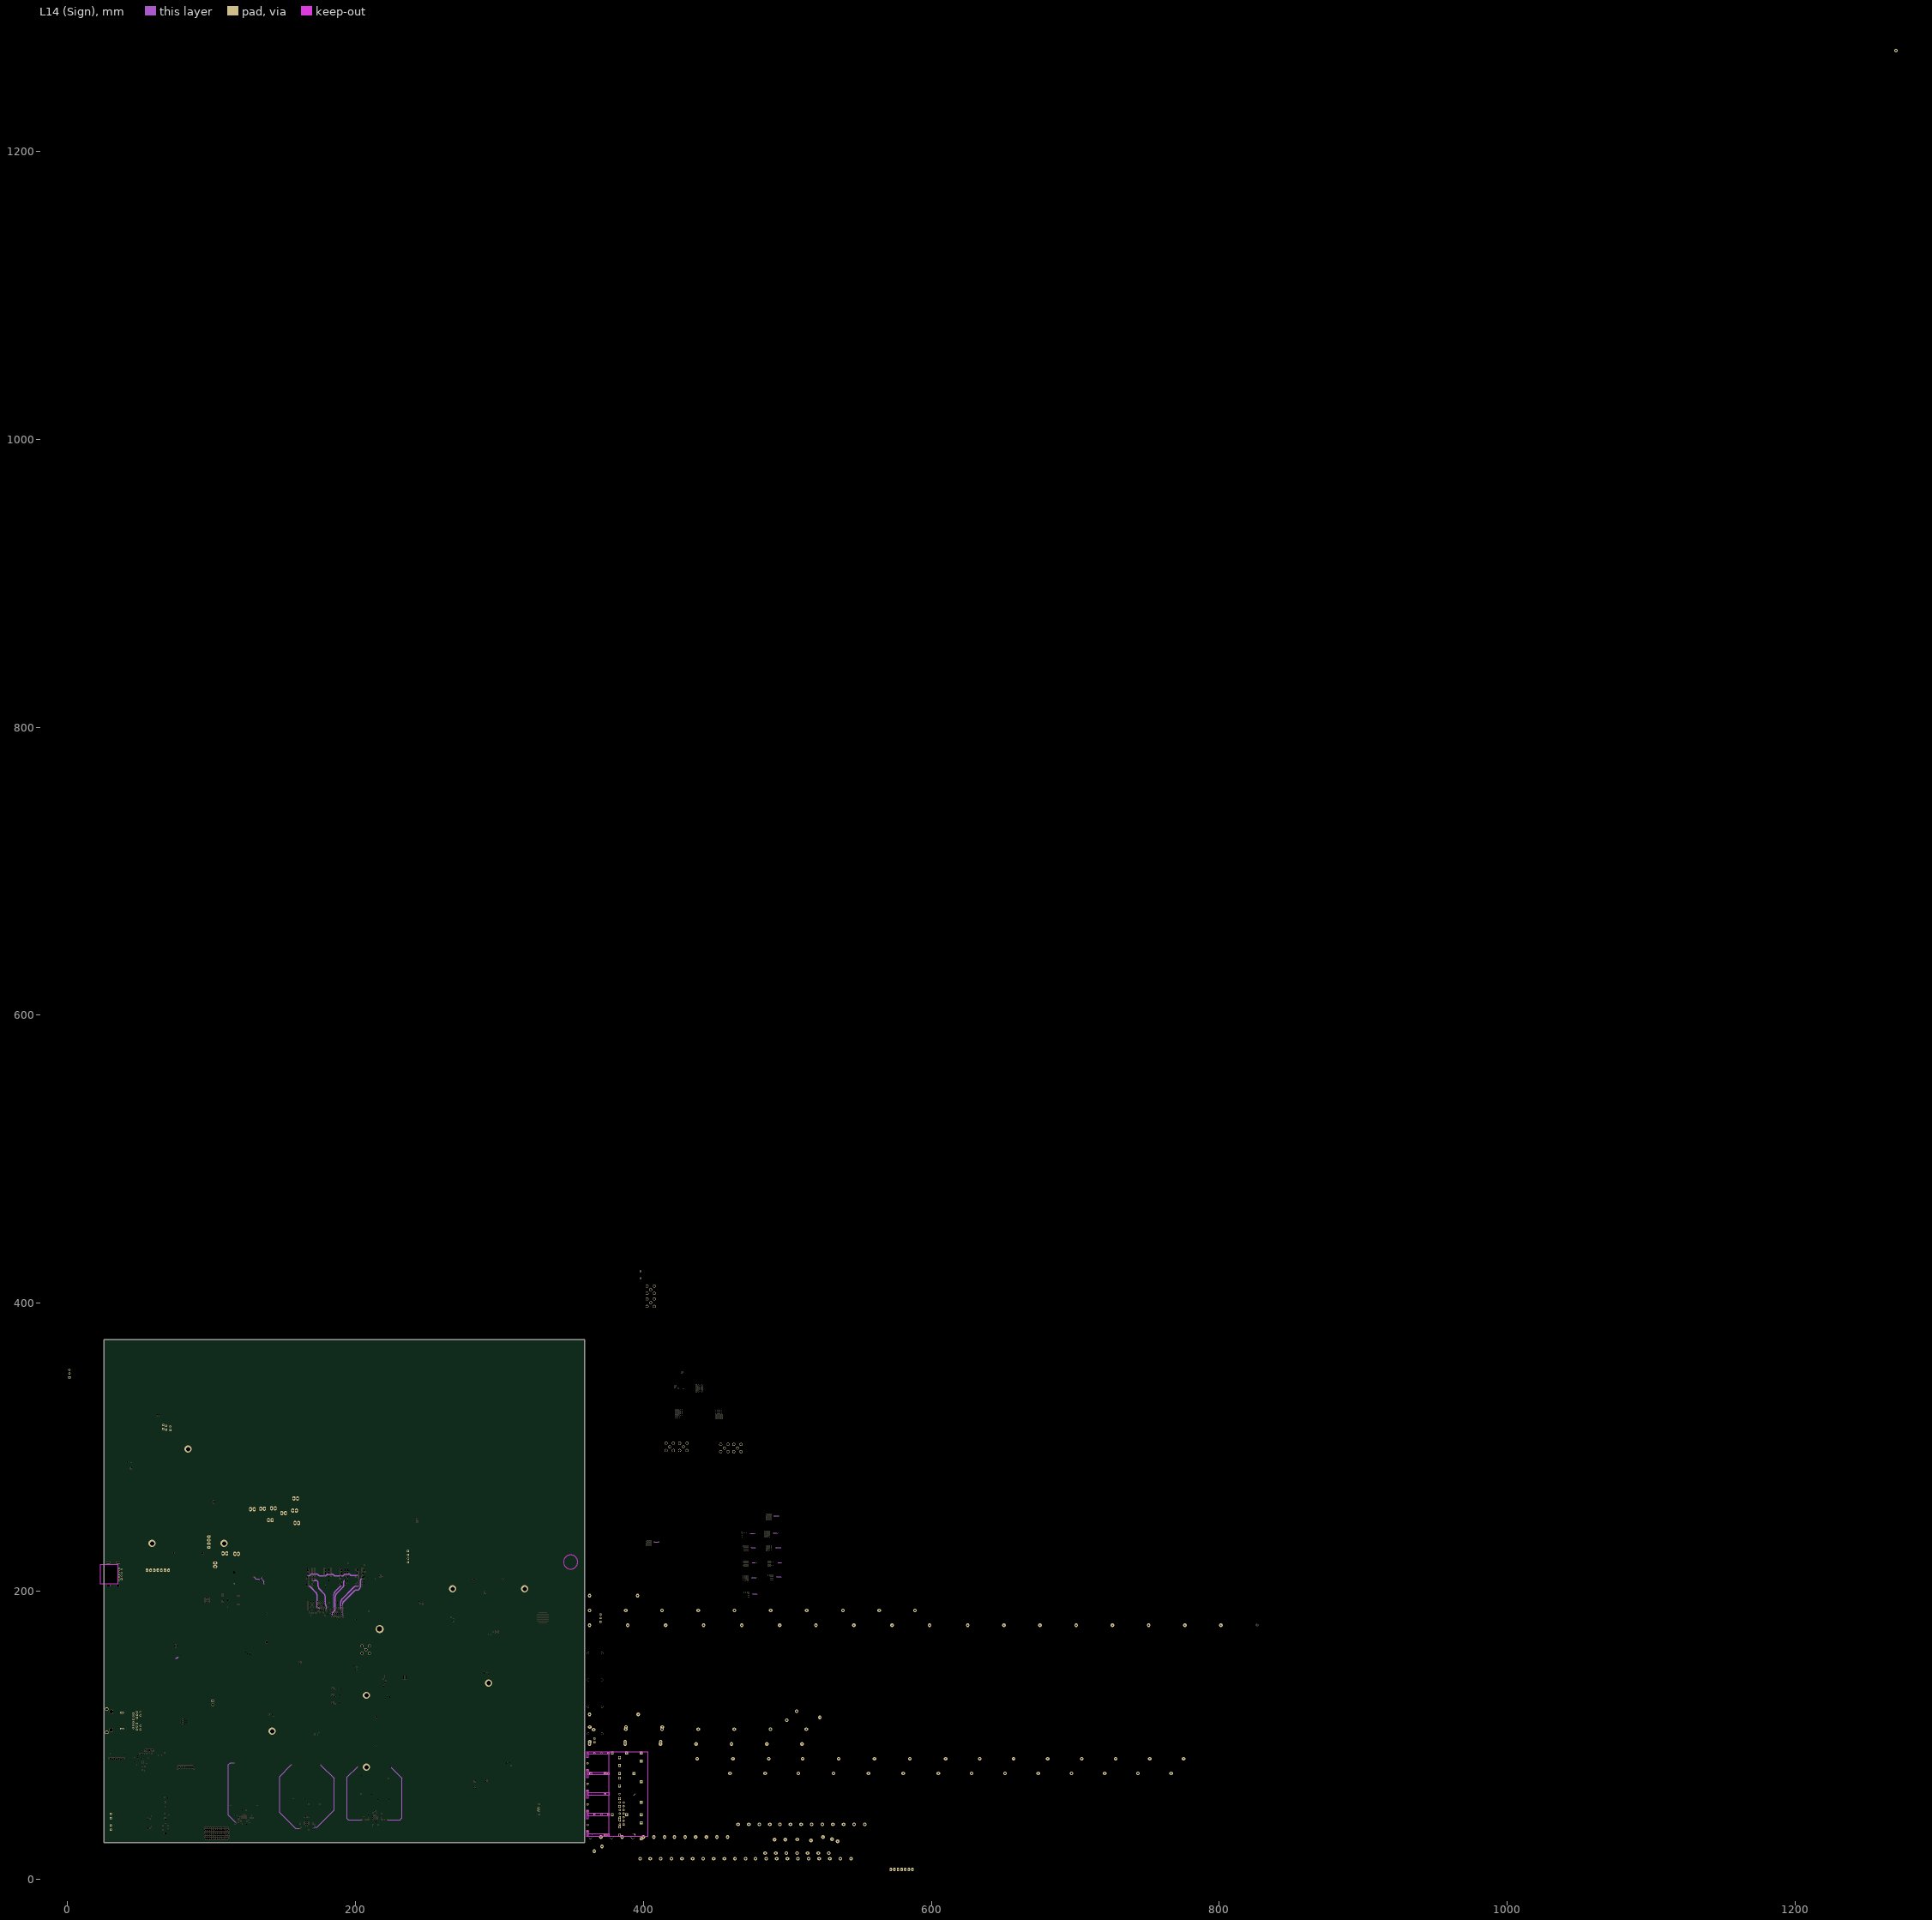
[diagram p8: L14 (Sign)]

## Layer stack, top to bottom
Top Solder: solder mask 0.025, SM-001, Dk 4
L1: signal copper 0.064
Dielectric 1: prepreg 0.074, PP-013, Dk 4.3
L2 (GND): signal copper 0.015
Dielectric 2: core 0.114, Core-001, Dk 4.1
L3 (Sign): signal copper 0.015
Dielectric 3: prepreg 0.114, PP-013, Dk 4.3
L4 (GND): signal copper 0.015
Dielectric 4: core 0.114, Core-001, Dk 4.1
L5 (Sign): signal copper 0.015
Dielectric 5: prepreg 0.114, PP-013, Dk 4.3
L6 (PWR/GND): signal copper 0.03
Dielectric 6: core 0.203, Core-001, Dk 4.1
L7(PWR/GND): signal copper 0.03
Dielectric 7: prepreg 0.203, PP-013, Dk 4.3
L8 (PWR/GND): signal copper 0.03
Dielectric 8: core 0.203, Core-001, Dk 4.1
L9 (PWR/GND): signal copper 0.03
Dielectric 9: prepreg 0.203, PP-013, Dk 4.3
L10 (PWR/GND): signal copper 0.03
Dielectric 10: core 0.203, Core-001, Dk 4.1
L11 (PWR/GND): signal copper 0.03
Dielectric 11: prepreg 0.114, PP-013, Dk 4.3
L12 (Sign): signal copper 0.015
Dielectric 12: core 0.114, Core-001, Dk 4.1
L13 (GND): signal copper 0.015
Dielectric 13: prepreg 0.114, PP-013, Dk 4.3
L14 (Sign): signal copper 0.015
Dielectric 14: core 0.114, Core-001, Dk 4.1
L15 (GND): signal copper 0.015
Dielectric 15: prepreg 0.074, PP-013, Dk 4.3
L16: signal copper 0.064
Bottom Solder: solder mask 0.025, SM-001, Dk 4

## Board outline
25.4,25.4 359.029,25.4 359.029,374.777 25.4,374.777

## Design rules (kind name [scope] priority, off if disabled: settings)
BackDrilling [(InNetClass('RAM_Adress') Or InNetClass('RAM_Data_IO') Or InNetClass('RAM_Clock_Signal') Or InNetClass('RAM_DQS_Strobe'))  And IsVia] p1: maxstublength=0.381 usetopbackdrill=TRUE usebottombackdrill=TRUE holeoversize=0.025 holetolplus=0 holetolminus=0
BoardOutlineClearance [All] p1: gap=0.254 ignorepadtopadclearanceinfootprint=FALSE except(0: Arc-SplitContinuation Track-SplitContinuation SMDPad-SplitContinuation THPad-SplitContinuation Via-SplitContinuation Fill-SplitContinuation Poly-SplitContinuation Region-SplitContinuation Text-SplitContinuation)
Clearance "RAM_Addr to RAM_Addr" [InNetClass('Single_36_39_50_Adr') vs InNetClass('Single_36_39_50_Adr')] p1: gap=0.1 ignorepadtopadclearanceinfootprint=FALSE
Clearance "RAM_Addr to other" [InNetClass('Single_36_39_50_Adr')] p2: gap=0.15 ignorepadtopadclearanceinfootprint=TRUE
Clearance [All] p3: gap=0.1 ignorepadtopadclearanceinfootprint=FALSE
DiffPairsRouting RAM_DQS [InDifferentialPairClass('Diff_76_to_90_Ram_DQS')] p1: maxlimit=0.254 minlimit=0.127 mostfreqgap=0.254 toplayer_maxgap=0.127 toplayer_prefgap=0.127 toplayer_minwidth=0.123 toplayer_maxwidth=0.159 toplayer_prefwidth=0.124 midlayer1_maxgap=0.127 midlayer1_prefgap=0.127 midlayer1_minwidth=0.105 midlayer1_maxwidth=0.105 midlayer1_prefwidth=0.105 midlayer2_maxgap=0.127 midlayer2_prefgap=0.127 midlayer2_minwidth=0.105 midlayer2_maxwidth=0.137 midlayer2_prefwidth=0.105 midlayer3_mingap=0.254 midlayer3_minwidth=0.381 midlayer3_maxwidth=0.381 midlayer3_prefwidth=0.381 midlayer4_mingap=0.254 midlayer4_minwidth=0.381 midlayer4_maxwidth=0.381 midlayer4_prefwidth=0.381 midlayer5_maxgap=0.127 midlayer5_prefgap=0.127 midlayer5_minwidth=0.105 midlayer5_maxwidth=0.127 midlayer5_prefwidth=0.105 midlayer6_maxgap=0.127 midlayer6_prefgap=0.127 midlayer6_minwidth=0.105 midlayer6_maxwidth=0.105 midlayer6_prefwidth=0.105 midlayer7_maxgap=0.127 midlayer7_prefgap=0.127 midlayer7_minwidth=0.084 midlayer7_maxwidth=0.084 midlayer7_prefwidth=0.084 midlayer8_maxgap=0.127 midlayer8_prefgap=0.127 midlayer8_minwidth=0.105 midlayer8_maxwidth=0.137 midlayer8_prefwidth=0.105 midlayer9_mingap=0.254 midlayer9_minwidth=0.381 midlayer9_maxwidth=0.381 midlayer9_prefwidth=0.381 midlayer10_mingap=0.254 midlayer10_minwidth=0.381 midlayer10_maxwidth=0.381 midlayer10_prefwidth=0.381 midlayer11_mingap=0.254 midlayer11_minwidth=0.381 midlayer11_maxwidth=0.381 midlayer11_prefwidth=0.381 midlayer12_mingap=0.254 midlayer12_minwidth=0.381 midlayer12_maxwidth=0.381 midlayer12_prefwidth=0.381 midlayer13_maxgap=0.127 midlayer13_prefgap=0.127 midlayer13_minwidth=0.105 midlayer13_maxwidth=0.137 midlayer13_prefwidth=0.105 midlayer14_maxgap=0.127 midlayer14_prefgap=0.127 midlayer14_minwidth=0.084 midlayer14_maxwidth=0.102 midlayer14_prefwidth=0.084 bottomlayer_maxgap=0.127 bottomlayer_prefgap=0.127 bottomlayer_minwidth=0.123 bottomlayer_maxwidth=0.159 bottomlayer_prefwidth=0.124 maxuncoupledlength=12.7
DiffPairsRouting RAM_Diff_76_86_90_Addr [InDifferentialPairClass('Diff_76_to_90_Ram_CLK')] p2: maxlimit=0.31 minlimit=0.111 mostfreqgap=0.254 toplayer_mingap=0.154 toplayer_prefgap=0.192 toplayer_minwidth=0.1 toplayer_maxwidth=0.12 toplayer_prefwidth=0.1 midlayer2_maxgap=0.262 midlayer2_prefgap=0.111 midlayer2_minwidth=0.1 midlayer2_maxwidth=0.12 midlayer2_prefwidth=0.1 midlayer5_maxgap=0.262 midlayer5_prefgap=0.111 midlayer5_minwidth=0.1 midlayer5_maxwidth=0.12 midlayer5_prefwidth=0.1 midlayer8_maxgap=0.262 midlayer8_prefgap=0.111 midlayer8_minwidth=0.1 midlayer8_maxwidth=0.12 midlayer8_prefwidth=0.1 midlayer13_maxgap=0.262 midlayer13_prefgap=0.111 midlayer13_minwidth=0.1 midlayer13_maxwidth=0.12 midlayer13_prefwidth=0.1 bottomlayer_mingap=0.154 bottomlayer_prefgap=0.192 bottomlayer_minwidth=0.1 bottomlayer_maxwidth=0.12 bottomlayer_prefwidth=0.1 impedanceprofiledriven=TRUE impedanceprofileid={1AFD27EA-460E-472B-BC44-4C5C59E93A8B} maxuncoupledlength=0.2 // Differential pair 86 Ohm
DiffPairsRouting Diff100 [InDifferentialPairClass('Diff_100')] p3: maxlimit=0.254 minlimit=0.127 mostfreqgap=0.254 toplayer_maxgap=0.127 toplayer_prefgap=0.127 toplayer_minwidth=0.045 toplayer_maxwidth=0.088 toplayer_prefwidth=0.045 midlayer1_maxgap=0.127 midlayer1_prefgap=0.127 midlayer1_minwidth=0.072 midlayer1_maxwidth=0.073 midlayer1_prefwidth=0.073 midlayer2_maxgap=0.127 midlayer2_prefgap=0.127 midlayer2_minwidth=0.072 midlayer2_maxwidth=0.073 midlayer2_prefwidth=0.073 midlayer5_maxgap=0.127 midlayer5_prefgap=0.127 midlayer5_minwidth=0.072 midlayer5_maxwidth=0.073 midlayer5_prefwidth=0.073 midlayer6_maxgap=0.127 midlayer6_prefgap=0.127 midlayer6_minwidth=0.072 midlayer6_maxwidth=0.073 midlayer6_prefwidth=0.073 midlayer7_maxgap=0.127 midlayer7_prefgap=0.127 midlayer7_minwidth=0.053 midlayer7_maxwidth=0.058 midlayer7_prefwidth=0.058 midlayer8_maxgap=0.127 midlayer8_prefgap=0.127 midlayer8_minwidth=0.072 midlayer8_maxwidth=0.073 midlayer8_prefwidth=0.073 midlayer13_maxgap=0.127 midlayer13_prefgap=0.127 midlayer13_minwidth=0.072 midlayer13_maxwidth=0.073 midlayer13_prefwidth=0.073 midlayer14_maxgap=0.127 midlayer14_prefgap=0.127 midlayer14_minwidth=0.053 midlayer14_maxwidth=0.058 midlayer14_prefwidth=0.058 bottomlayer_maxgap=0.127 bottomlayer_prefgap=0.127 bottomlayer_minwidth=0.045 bottomlayer_maxwidth=0.088 bottomlayer_prefwidth=0.045 impedanceprofiledriven=TRUE impedanceprofileid={3149E961-6C2D-4C90-A41E-90A05D6C6F09} maxuncoupledlength=12.7 // Differential 100 Ohm
DiffPairsRouting "Diff 90" [InDifferentialPairClass('Diff_90')] p4: maxlimit=0.254 minlimit=0.127 mostfreqgap=0.254 toplayer_maxgap=0.127 toplayer_prefgap=0.127 toplayer_minwidth=0.045 toplayer_maxwidth=0.088 toplayer_prefwidth=0.045 midlayer1_maxgap=0.127 midlayer1_prefgap=0.127 midlayer1_minwidth=0.072 midlayer1_maxwidth=0.073 midlayer1_prefwidth=0.073 midlayer2_maxgap=0.127 midlayer2_prefgap=0.127 midlayer2_minwidth=0.072 midlayer2_maxwidth=0.073 midlayer2_prefwidth=0.073 midlayer5_maxgap=0.127 midlayer5_prefgap=0.127 midlayer5_minwidth=0.072 midlayer5_maxwidth=0.073 midlayer5_prefwidth=0.073 midlayer6_maxgap=0.127 midlayer6_prefgap=0.127 midlayer6_minwidth=0.072 midlayer6_maxwidth=0.073 midlayer6_prefwidth=0.073 midlayer7_maxgap=0.127 midlayer7_prefgap=0.127 midlayer7_minwidth=0.053 midlayer7_maxwidth=0.058 midlayer7_prefwidth=0.058 midlayer8_maxgap=0.127 midlayer8_prefgap=0.127 midlayer8_minwidth=0.072 midlayer8_maxwidth=0.073 midlayer8_prefwidth=0.073 midlayer13_maxgap=0.127 midlayer13_prefgap=0.127 midlayer13_minwidth=0.072 midlayer13_maxwidth=0.073 midlayer13_prefwidth=0.073 midlayer14_maxgap=0.127 midlayer14_prefgap=0.127 midlayer14_minwidth=0.053 midlayer14_maxwidth=0.058 midlayer14_prefwidth=0.058 bottomlayer_maxgap=0.127 bottomlayer_prefgap=0.127 bottomlayer_minwidth=0.045 bottomlayer_maxwidth=0.088 bottomlayer_prefwidth=0.045 impedanceprofiledriven=TRUE impedanceprofileid={3149E961-6C2D-4C90-A41E-90A05D6C6F09} maxuncoupledlength=12.7 // Differential 90 Ohm
HoleSize DrillHole [All] p1: absolutevalues=TRUE maxlimit=5 minlimit=0.1 maxpercent=80.000 minpercent=20.000
HoleToHoleClearance [All] p1: gap=0.1 allowstackedmicrovias=TRUE
MatchedLengths MatchedLengths_DDR_CLOCKS_STROBES [InxSignalClass('ADDR_PP1') OR InxSignalClass('ADDR_PP2') OR InxSignalClass('ADDR_PP3') OR InxSignalClass('ADDR_PP4') OR InxSignalClass('DATA_BL0') OR InxSignalClass('DATA_BL1') OR InxSignalClass('DATA_BL2') OR InxSignalClass('DATA_BL3') OR InxSignalClass('DATA_BL4') OR InxSignalClass('DATA_BL5') OR InxSignalClass('DATA_BL6') OR InxSignalClass('DATA_BL7')] p1: tolerance=0.305 checknetsindiffpair=TRUE checkdiffpairvsdiffpair=FALSE checkxsignals=FALSE checkothers=FALSE
MatchedLengths MatchedLengths_DATA_BL7 [InxSignalClass('DATA_BL7')] p2: tolerance=1.473 checknetsindiffpair=FALSE checkdiffpairvsdiffpair=TRUE checkxsignals=TRUE checkothers=TRUE
MatchedLengths MatchedLengths_DATA_BL6 [InxSignalClass('DATA_BL6')] p3: tolerance=1.473 checknetsindiffpair=FALSE checkdiffpairvsdiffpair=TRUE checkxsignals=TRUE checkothers=TRUE
MatchedLengths MatchedLengths_DATA_BL5 [InxSignalClass('DATA_BL5')] p4: tolerance=1.473 checknetsindiffpair=FALSE checkdiffpairvsdiffpair=TRUE checkxsignals=TRUE checkothers=TRUE
MatchedLengths MatchedLengths_DATA_BL4 [InxSignalClass('DATA_BL4')] p5: tolerance=1.473 checknetsindiffpair=FALSE checkdiffpairvsdiffpair=TRUE checkxsignals=TRUE checkothers=TRUE
MatchedLengths MatchedLengths_DATA_BL3 [InxSignalClass('DATA_BL3')] p6: tolerance=1.473 checknetsindiffpair=FALSE checkdiffpairvsdiffpair=TRUE checkxsignals=TRUE checkothers=TRUE
MatchedLengths MatchedLengths_DATA_BL2 [InxSignalClass('DATA_BL2')] p7: tolerance=1.473 checknetsindiffpair=FALSE checkdiffpairvsdiffpair=TRUE checkxsignals=TRUE checkothers=TRUE
MatchedLengths MatchedLengths_DATA_BL1 [InxSignalClass('DATA_BL1')] p8: tolerance=1.473 checknetsindiffpair=FALSE checkdiffpairvsdiffpair=TRUE checkxsignals=TRUE checkothers=TRUE
MatchedLengths MatchedLengths_DATA_BL0 [InxSignalClass('DATA_BL0')] p9: tolerance=1.473 checknetsindiffpair=FALSE checkdiffpairvsdiffpair=TRUE checkxsignals=TRUE checkothers=TRUE
MatchedLengths MatchedLengths_ADDR_PP4 [InxSignalClass('ADDR_PP4')] p10 off: tolerance=1.194 checknetsindiffpair=FALSE checkdiffpairvsdiffpair=TRUE checkxsignals=TRUE checkothers=TRUE
MatchedLengths MatchedLengths_ADDR_PP3 [InxSignalClass('ADDR_PP3')] p11 off: tolerance=1.194 checknetsindiffpair=FALSE checkdiffpairvsdiffpair=TRUE checkxsignals=TRUE checkothers=TRUE
MatchedLengths MatchedLengths_ADDR_PP2 [InxSignalClass('ADDR_PP2')] p12: tolerance=1.194 checknetsindiffpair=FALSE checkdiffpairvsdiffpair=TRUE checkxsignals=TRUE checkothers=TRUE
MatchedLengths MatchedLengths_ADDR_PP1 [InxSignalClass('ADDR_PP1')] p13: tolerance=1.194 checknetsindiffpair=FALSE checkdiffpairvsdiffpair=TRUE checkxsignals=TRUE checkothers=TRUE
MatchedLengths SFP_Data [InNetClass('SFP_diff')] p14: tolerance=0.305 checknetsindiffpair=FALSE checkdiffpairvsdiffpair=TRUE checkxsignals=TRUE checkothers=TRUE
MatchedLengths DiferentialPairSkew [All] p15: tolerance=25.4 checknetsindiffpair=TRUE checkdiffpairvsdiffpair=FALSE checkxsignals=FALSE checkothers=FALSE
MatchedLengths RAM_Data_to_DQS [InNetClass('Lenght_DQS_to_Data')] p16 off: tolerance=25.4 checknetsindiffpair=FALSE checkdiffpairvsdiffpair=TRUE checkxsignals=TRUE checkothers=TRUE
MatchedLengths RAM_DQS_to_CK [InNetClass('Lenght_DQS_to_CK')] p17 off: tolerance=25.4 checknetsindiffpair=FALSE checkdiffpairvsdiffpair=TRUE checkxsignals=TRUE checkothers=TRUE
MatchedLengths MatchedLengths_DDR_DQS [InNetClass('RAM_DQS_Strobe')] p18 off: tolerance=0.305 checknetsindiffpair=TRUE checkdiffpairvsdiffpair=FALSE checkxsignals=FALSE checkothers=FALSE
MatchedLengths RAM_Addr_LenghMatch [InNetClass('RAM_Adress')] p19 off: tolerance=0.305 checknetsindiffpair=FALSE checkdiffpairvsdiffpair=TRUE checkxsignals=TRUE checkothers=TRUE
MatchedLengths Ram_Addr_Com_Ctrl_to_CK [InNetClass('Lenght_CK_to_Addr')] p20 off: tolerance=0.305 checknetsindiffpair=FALSE checkdiffpairvsdiffpair=TRUE checkxsignals=TRUE checkothers=TRUE
MatchedLengths RAM_MatchedLengths_DATA_IO [InNetClass('RAM_Data_IO')] p21 off: tolerance=0.305 checknetsindiffpair=FALSE checkdiffpairvsdiffpair=TRUE checkxsignals=TRUE checkothers=TRUE
MinimumAnnularRing DefRing [All] p1: minimumring=0.15
MinimumSolderMaskSliver [All] p1: minsoldermaskwidth=0.1
PlaneConnect [All] p1: planeconnectstyle=Direct reliefexpansion=0.508 reliefentries=4 reliefconductorwidth=0.254 reliefairgap=0.254
PolygonConnect [All] p1: connectstyle=Direct reliefconductorwidth=0.254 reliefentries=4 polygonreliefangle="90 Angle" airgapwidth=0.254
RoomDefinition 5V_to_3V3_for_FTDI [InComponentClass('5V_to_3V3_for_FTDI')] p1: confinementstyle=ConfineIn formatcopy=TRUE lockcomponents=FALSE outline 0,0 50.8,0 50.8,25.4 0,25.4
RoomDefinition I2C_Expander_16 [InComponentClass('I2C_Expander_16')] p2: confinementstyle=ConfineIn formatcopy=TRUE lockcomponents=FALSE outline 0,0 50.8,0 50.8,25.4 0,25.4
RoomDefinition I2C_Expander_15 [InComponentClass('I2C_Expander_15')] p3: confinementstyle=ConfineIn formatcopy=TRUE lockcomponents=FALSE outline 0,0 50.8,0 50.8,25.4 0,25.4
RoomDefinition I2C_Expander_14 [InComponentClass('I2C_Expander_14')] p4: confinementstyle=ConfineIn formatcopy=TRUE lockcomponents=FALSE outline 0,0 50.8,0 50.8,25.4 0,25.4
RoomDefinition I2C_Expander_13 [InComponentClass('I2C_Expander_13')] p5: confinementstyle=ConfineIn formatcopy=TRUE lockcomponents=FALSE outline 0,0 50.8,0 50.8,25.4 0,25.4
RoomDefinition I2C_Expander_12 [InComponentClass('I2C_Expander_12')] p6: confinementstyle=ConfineIn formatcopy=TRUE lockcomponents=FALSE outline 0,0 50.8,0 50.8,25.4 0,25.4
RoomDefinition I2C_Expander_11 [InComponentClass('I2C_Expander_11')] p7: confinementstyle=ConfineIn formatcopy=TRUE lockcomponents=FALSE outline 0,0 50.8,0 50.8,25.4 0,25.4
RoomDefinition I2C_Expander_10 [InComponentClass('I2C_Expander_10')] p8: confinementstyle=ConfineIn formatcopy=TRUE lockcomponents=FALSE outline 0,0 50.8,0 50.8,25.4 0,25.4
RoomDefinition I2C_Expander? [InComponentClass('I2C_Expander?')] p9: confinementstyle=ConfineIn formatcopy=TRUE lockcomponents=FALSE outline 0,0 50.8,0 50.8,25.4 0,25.4
RoomDefinition U_TPS7A88_3V3_1V8_0V9V@2x1A [InComponentClass('U_TPS7A88_3V3_1V8_0V9V@2x1A')] p10: confinementstyle=ConfineIn formatcopy=TRUE lockcomponents=FALSE outline 0,0 50.8,0 50.8,25.4 0,25.4
RoomDefinition U_Pomiar_pradu_napiecia_11 [InComponentClass('U_Pomiar_pradu_napiecia_11')] p11: confinementstyle=ConfineIn formatcopy=TRUE lockcomponents=FALSE outline 0,0 50.8,0 50.8,25.4 0,25.4
RoomDefinition U_Pomiar_pradu_napiecia_10 [InComponentClass('U_Pomiar_pradu_napiecia_10')] p12: confinementstyle=ConfineIn formatcopy=TRUE lockcomponents=FALSE outline 0,0 50.8,0 50.8,25.4 0,25.4
RoomDefinition U_Pomiar_pradu_napiecia_9 [InComponentClass('U_Pomiar_pradu_napiecia_9')] p13: confinementstyle=ConfineIn formatcopy=TRUE lockcomponents=FALSE outline 0,0 50.8,0 50.8,25.4 0,25.4
RoomDefinition U_Pomiar_pradu_napiecia_8 [InComponentClass('U_Pomiar_pradu_napiecia_8')] p14: confinementstyle=ConfineIn formatcopy=TRUE lockcomponents=FALSE outline 0,0 50.8,0 50.8,25.4 0,25.4
RoomDefinition U_Pomiar_pradu_napiecia_7 [InComponentClass('U_Pomiar_pradu_napiecia_7')] p15: confinementstyle=ConfineIn formatcopy=TRUE lockcomponents=FALSE outline 0,0 50.8,0 50.8,25.4 0,25.4
RoomDefinition U_Pomiar_pradu_napiecia_6 [InComponentClass('U_Pomiar_pradu_napiecia_6')] p16: confinementstyle=ConfineIn formatcopy=TRUE lockcomponents=FALSE outline 0,0 50.8,0 50.8,25.4 0,25.4
RoomDefinition U_Pomiar_pradu_napiecia_5 [InComponentClass('U_Pomiar_pradu_napiecia_5')] p17: confinementstyle=ConfineIn formatcopy=TRUE lockcomponents=FALSE outline 0,0 50.8,0 50.8,25.4 0,25.4
RoomDefinition U_Pomiar_pradu_napiecia_4 [InComponentClass('U_Pomiar_pradu_napiecia_4')] p18: confinementstyle=ConfineIn formatcopy=TRUE lockcomponents=FALSE outline 0,0 50.8,0 50.8,25.4 0,25.4
RoomDefinition U_Pomiar_pradu_napiecia_3 [InComponentClass('U_Pomiar_pradu_napiecia_3')] p19: confinementstyle=ConfineIn formatcopy=TRUE lockcomponents=FALSE outline 0,0 50.8,0 50.8,25.4 0,25.4
RoomDefinition U_Pomiar_pradu_napiecia_2 [InComponentClass('U_Pomiar_pradu_napiecia_2')] p20: confinementstyle=ConfineIn formatcopy=TRUE lockcomponents=FALSE outline 0,0 50.8,0 50.8,25.4 0,25.4
RoomDefinition U_5V_to_3V32 [InComponentClass('U_5V_to_3V32')] p21: confinementstyle=ConfineIn formatcopy=TRUE lockcomponents=FALSE outline 0,0 50.8,0 50.8,25.4 0,25.4
RoomDefinition U_5V_to_3V31 [InComponentClass('U_5V_to_3V31')] p22: confinementstyle=ConfineIn formatcopy=TRUE lockcomponents=FALSE outline 0,0 50.8,0 50.8,25.4 0,25.4
RoomDefinition SFP_Group+IMU [InComponentClass('SFP_Group+IMU')] p23: confinementstyle=ConfineIn formatcopy=TRUE lockcomponents=FALSE outline 0,0 50.8,0 50.8,25.4 0,25.4
RoomDefinition IMU [InComponentClass('IMU')] p24: confinementstyle=ConfineIn formatcopy=TRUE lockcomponents=FALSE outline 0,0 50.8,0 50.8,25.4 0,25.4
RoomDefinition I2C_Expander3 [InComponentClass('I2C_Expander3')] p25: confinementstyle=ConfineIn formatcopy=TRUE lockcomponents=FALSE outline 0,0 50.8,0 50.8,25.4 0,25.4
RoomDefinition I2C_Expander2 [InComponentClass('I2C_Expander2')] p26: confinementstyle=ConfineIn formatcopy=TRUE lockcomponents=FALSE outline 0,0 50.8,0 50.8,25.4 0,25.4
RoomDefinition I2C_Expander1 [InComponentClass('I2C_Expander1')] p27: confinementstyle=ConfineIn formatcopy=TRUE lockcomponents=FALSE outline 0,0 50.8,0 50.8,25.4 0,25.4
RoomDefinition HighSpeed [InComponentClass('HighSpeed')] p28: confinementstyle=ConfineIn formatcopy=TRUE lockcomponents=FALSE outline 0,0 50.8,0 50.8,25.4 0,25.4
RoomDefinition GTR [InComponentClass('GTR')] p29: confinementstyle=ConfineIn formatcopy=TRUE lockcomponents=FALSE outline 0,0 50.8,0 50.8,25.4 0,25.4
RoomDefinition Flash_Memory [InComponentClass('Flash_Memory')] p30: confinementstyle=ConfineIn formatcopy=TRUE lockcomponents=FALSE outline 0,0 50.8,0 50.8,25.4 0,25.4
RoomDefinition Ext_GPIO [InComponentClass('Ext_GPIO')] p31: confinementstyle=ConfineIn formatcopy=TRUE lockcomponents=FALSE outline 0,0 50.8,0 50.8,25.4 0,25.4
RoomDefinition DAC [InComponentClass('DAC')] p32: confinementstyle=ConfineIn formatcopy=TRUE lockcomponents=FALSE outline 0,0 50.8,0 50.8,25.4 0,25.4
RoomDefinition "Bank 226" [InComponentClass('Bank 226')] p33: confinementstyle=ConfineIn formatcopy=TRUE lockcomponents=FALSE outline 0,0 50.8,0 50.8,25.4 0,25.4
RoomDefinition "Bank 225" [InComponentClass('Bank 225')] p34: confinementstyle=ConfineIn formatcopy=TRUE lockcomponents=FALSE outline 0,0 50.8,0 50.8,25.4 0,25.4
RoomDefinition "Bank 224" [InComponentClass('Bank 224')] p35: confinementstyle=ConfineIn formatcopy=TRUE lockcomponents=FALSE outline 0,0 50.8,0 50.8,25.4 0,25.4
RoomDefinition "Bank 223" [InComponentClass('Bank 223')] p36: confinementstyle=ConfineIn formatcopy=TRUE lockcomponents=FALSE outline 0,0 50.8,0 50.8,25.4 0,25.4
RoomDefinition USB3.0 [InComponentClass('USB3.0')] p37: confinementstyle=ConfineIn formatcopy=TRUE lockcomponents=FALSE outline 0,0 50.8,0 50.8,25.4 0,25.4
RoomDefinition U_Pomiar_pradu_napiecia_1 [InComponentClass('U_Pomiar_pradu_napiecia_1')] p38: confinementstyle=ConfineIn formatcopy=TRUE lockcomponents=FALSE outline 0,0 50.8,0 50.8,25.4 0,25.4
RoomDefinition U_Pomiar_napiecia_high_curr [InComponentClass('U_Pomiar_napiecia_high_curr')] p39: confinementstyle=ConfineIn formatcopy=TRUE lockcomponents=FALSE outline 0,0 50.8,0 50.8,25.4 0,25.4
RoomDefinition U_FPGA_Decoupling [InComponentClass('U_FPGA_Decoupling')] p40: confinementstyle=ConfineIn formatcopy=TRUE lockcomponents=FALSE outline 0,0 50.8,0 50.8,25.4 0,25.4
RoomDefinition U_Expander_RESET [InComponentClass('U_Expander_RESET')] p41: confinementstyle=ConfineIn formatcopy=TRUE lockcomponents=FALSE outline 0,0 50.8,0 50.8,25.4 0,25.4
RoomDefinition U_CAN [InComponentClass('U_CAN')] p42: confinementstyle=ConfineIn formatcopy=TRUE lockcomponents=FALSE outline 0,0 50.8,0 50.8,25.4 0,25.4
RoomDefinition PS_Config [InComponentClass('PS_Config')] p43: confinementstyle=ConfineIn formatcopy=TRUE lockcomponents=FALSE outline 0,0 50.8,0 50.8,25.4 0,25.4
RoomDefinition NVMe [InComponentClass('NVMe')] p44: confinementstyle=ConfineIn formatcopy=TRUE lockcomponents=FALSE outline 0,0 50.8,0 50.8,25.4 0,25.4
RoomDefinition "Gigabit Eth" [InComponentClass('Gigabit Eth')] p45: confinementstyle=ConfineIn formatcopy=TRUE lockcomponents=FALSE outline 0,0 50.8,0 50.8,25.4 0,25.4
RoomDefinition Debug [InComponentClass('Debug')] p46: confinementstyle=ConfineIn formatcopy=TRUE lockcomponents=FALSE outline 0,0 50.8,0 50.8,25.4 0,25.4
RoomDefinition CLK_MUX [InComponentClass('CLK_MUX')] p47: confinementstyle=ConfineIn formatcopy=TRUE lockcomponents=FALSE outline 0,0 50.8,0 50.8,25.4 0,25.4
RoomDefinition µSD [InComponentClass('µSD')] p48: confinementstyle=ConfineIn formatcopy=TRUE lockcomponents=FALSE outline 0,0 50.8,0 50.8,25.4 0,25.4
RoomDefinition U_UM78M_12_8V [InComponentClass('U_UM78M_12_8V')] p49: confinementstyle=ConfineIn formatcopy=TRUE lockcomponents=FALSE outline 0,0 50.8,0 50.8,25.4 0,25.4
RoomDefinition U_TPS7A88_5V_Dual_3 [InComponentClass('U_TPS7A88_5V_Dual_3')] p50: confinementstyle=ConfineIn formatcopy=TRUE lockcomponents=FALSE outline 0,0 50.8,0 50.8,25.4 0,25.4
RoomDefinition U_ST1L08_5V_0V6 [InComponentClass('U_ST1L08_5V_0V6')] p51: confinementstyle=ConfineIn formatcopy=TRUE lockcomponents=FALSE outline 0,0 50.8,0 50.8,25.4 0,25.4
RoomDefinition U_Power_Ethernet [InComponentClass('U_Power_Ethernet')] p52: confinementstyle=ConfineIn formatcopy=TRUE lockcomponents=FALSE outline 0,0 50.8,0 50.8,25.4 0,25.4
RoomDefinition U_Power_ADP1850_Dual_2 [InComponentClass('U_Power_ADP1850_Dual_2')] p53: confinementstyle=ConfineIn formatcopy=TRUE lockcomponents=FALSE outline 0,0 50.8,0 50.8,25.4 0,25.4
RoomDefinition U_Power_48_20V@3A [InComponentClass('U_Power_48_20V@3A')] p54: confinementstyle=ConfineIn formatcopy=TRUE lockcomponents=FALSE outline 0,0 50.8,0 50.8,25.4 0,25.4
RoomDefinition U_LT3042_12V_5V_LNLDO [InComponentClass('U_LT3042_12V_5V_LNLDO')] p55: confinementstyle=ConfineIn formatcopy=TRUE lockcomponents=FALSE outline 0,0 50.8,0 50.8,25.4 0,25.4
RoomDefinition U_HI_Curr_ADP1850_3 [InComponentClass('U_HI_Curr_ADP1850_3')] p56: confinementstyle=ConfineIn formatcopy=TRUE lockcomponents=FALSE outline 0,0 50.8,0 50.8,25.4 0,25.4
RoomDefinition U_HI_Curr_ADP1850_1 [InComponentClass('U_HI_Curr_ADP1850_1')] p57: confinementstyle=ConfineIn formatcopy=TRUE lockcomponents=FALSE outline 0,0 50.8,0 50.8,25.4 0,25.4
RoomDefinition U_Detektor_otwarcia [InComponentClass('U_Detektor_otwarcia')] p58: confinementstyle=ConfineIn formatcopy=TRUE lockcomponents=FALSE outline 0,0 50.8,0 50.8,25.4 0,25.4
RoomDefinition U_ADP1741_3V3_0V85 [InComponentClass('U_ADP1741_3V3_0V85')] p59: confinementstyle=ConfineIn formatcopy=TRUE lockcomponents=FALSE outline 0,0 50.8,0 50.8,25.4 0,25.4
RoomDefinition U_ADP1741_3 [InComponentClass('U_ADP1741_3')] p60: confinementstyle=ConfineIn formatcopy=TRUE lockcomponents=FALSE outline 0,0 50.8,0 50.8,25.4 0,25.4
RoomDefinition U_5V_to_3V33 [InComponentClass('U_5V_to_3V33')] p61: confinementstyle=ConfineIn formatcopy=TRUE lockcomponents=FALSE outline 0,0 50.8,0 50.8,25.4 0,25.4
RoutingTopology RoutingTopology_DDRAddressAndControls [InNetClass('DDR_AddressAndControls')] p1: topology=Daisy_Simple
RoutingTopology [All] p2: topology=Shortest
RoutingVias BackDrilled_1-5 [InDrillLayerPair('[BD] L5 (Sign) - L16')] p1: holewidth=0.2 width=0.5 viastyle="Through Hole" minholewidth=0.2 minwidth=0.5 maxholewidth=0.2 maxwidth=0.5
RoutingVias BackDrilled_1-14 [InDrillLayerPair('[BD] L14 (Sign) - L16')] p2: holewidth=0.2 width=0.5 viastyle="Through Hole" minholewidth=0.2 minwidth=0.5 maxholewidth=0.2 maxwidth=0.5
RoutingVias BackDrilled_1-12 [InDrillLayerPair('[BD] L12 (Sign) - L16')] p3: holewidth=0.2 width=0.5 viastyle="Through Hole" minholewidth=0.2 minwidth=0.5 maxholewidth=0.2 maxwidth=0.5
RoutingVias Vi14-16 [InDrillLayerPair('[UVIA] L14 (Sign) - L16')] p4: holewidth=0.127 width=0.35 viastyle="Through Hole" minholewidth=0.1 minwidth=0.2 maxholewidth=0.127 maxwidth=0.35
RoutingVias UVia1-2 [InDrillLayerPair('[UVIA] L1 - L2 (GND)')] p5: holewidth=0.127 width=0.35 viastyle="Through Hole" minholewidth=0.127 minwidth=0.35 maxholewidth=0.127 maxwidth=0.35
RoutingVias UVia1-3 [InDrillLayerPair('[UVIA] L1 - L3 (Sign)')] p6: holewidth=0.127 width=0.35 viastyle="Through Hole" minholewidth=0.1 minwidth=0.2 maxholewidth=0.127 maxwidth=0.35
RoutingVias UVia16-15 [InDrillLayerPair('[UVIA] L15 (GND) - L16')] p7: holewidth=0.127 width=0.35 viastyle="Through Hole" minholewidth=0.1 minwidth=0.2 maxholewidth=0.127 maxwidth=0.35
RoutingVias UVia14-15 [InDrillLayerPair('No Drill Pair')] p8: holewidth=0.127 width=0.35 viastyle="Through Hole" minholewidth=0.127 minwidth=0.35 maxholewidth=0.127 maxwidth=0.35
RoutingVias Diff_Pair_Via [InDifferentialPairClass('All Differential Pairs')] p9: holewidth=0.2 width=0.4 viastyle="Through Hole" minholewidth=0.127 minwidth=0.35 maxholewidth=0.3 maxwidth=0.5
RoutingVias [All] p10: holewidth=0.2 width=0.5 viastyle="Through Hole" minholewidth=0.1 minwidth=0.2 maxholewidth=2 maxwidth=2.25
SilkToSilkClearance [All] p1: silktosilkclearance=0.1
SilkToSolderMaskClearance [IsPad] p1: minsilkscreentomaskgap=0 clearancetoexposedcopper=TRUE
SolderMaskExpansion [All] p1: expansion=0.102
Width Power_Line_1 [All] p1: maxlimit=2 minlimit=0.164 preferedwidth=0.912
Width Power_Line_2 [InNetClass('Power_Line_2A')] p2: maxlimit=4.8 minlimit=0.428 preferedwidth=2.37
Width Power_Line_20 [InNetClass('Power_Line_20A')] p3: maxlimit=100 minlimit=7 preferedwidth=50
Width Power_Line_40 [InNetClass('Power_Line_40A')] p4: maxlimit=300 minlimit=26.6 preferedwidth=148
Width Single_Ram_CLK [InNetClass('RAM_Clock_Signal')] p5: maxlimit=0.152 minlimit=0.102 preferedwidth=0.127
Width Single_RAM_Com [InNetClass('RAM_Adress')] p6: maxlimit=0.254 minlimit=0.068 preferedwidth=0.254 toplayer_minwidth=0.116 toplayer_maxwidth=0.211 toplayer_prefwidth=0.184 midlayer1_minwidth=0.092 midlayer1_maxwidth=0.173 midlayer1_prefwidth=0.151 midlayer2_minwidth=0.092 midlayer2_maxwidth=0.173 midlayer2_prefwidth=0.151 midlayer3_minwidth=0.254 midlayer4_minwidth=0.254 midlayer5_minwidth=0.092 midlayer5_maxwidth=0.173 midlayer5_prefwidth=0.151 midlayer6_minwidth=0.092 midlayer6_maxwidth=0.173 midlayer6_prefwidth=0.151 midlayer7_maxwidth=0.132 midlayer7_prefwidth=0.114 midlayer8_minwidth=0.092 midlayer8_maxwidth=0.173 midlayer8_prefwidth=0.151 midlayer9_minwidth=0.092 midlayer9_prefwidth=0.151 midlayer10_minwidth=0.254 midlayer11_minwidth=0.254 midlayer12_minwidth=0.254 midlayer13_minwidth=0.092 midlayer13_maxwidth=0.173 midlayer13_prefwidth=0.151 midlayer14_maxwidth=0.132 midlayer14_prefwidth=0.114 bottomlayer_minwidth=0.116 bottomlayer_maxwidth=0.211 bottomlayer_prefwidth=0.184 minimp=50.000000 maximp=50.000000 favimp=50.000000 // Track's for Adress, comands and control
Width SingleRam_Data [InNetClass('RAM_Data_IO')] p7: maxlimit=0.254 minlimit=0.068 preferedwidth=0.254 toplayer_minwidth=0.116 toplayer_maxwidth=0.211 toplayer_prefwidth=0.184 midlayer1_minwidth=0.092 midlayer1_maxwidth=0.173 midlayer1_prefwidth=0.151 midlayer2_minwidth=0.092 midlayer2_maxwidth=0.173 midlayer2_prefwidth=0.151 midlayer3_minwidth=0.254 midlayer4_minwidth=0.254 midlayer5_minwidth=0.092 midlayer5_maxwidth=0.173 midlayer5_prefwidth=0.151 midlayer6_minwidth=0.092 midlayer6_maxwidth=0.173 midlayer6_prefwidth=0.151 midlayer7_maxwidth=0.132 midlayer7_prefwidth=0.114 midlayer8_minwidth=0.092 midlayer8_maxwidth=0.173 midlayer8_prefwidth=0.151 midlayer9_minwidth=0.092 midlayer9_prefwidth=0.151 midlayer10_minwidth=0.254 midlayer11_minwidth=0.254 midlayer12_minwidth=0.254 midlayer13_minwidth=0.092 midlayer13_maxwidth=0.173 midlayer13_prefwidth=0.151 midlayer14_maxwidth=0.132 midlayer14_prefwidth=0.114 bottomlayer_minwidth=0.116 bottomlayer_maxwidth=0.211 bottomlayer_prefwidth=0.184 minimp=50.000000 maximp=50.000000 favimp=50.000000 // Track's for comand in r
Width Single45 [InNetClass('Single_45')] p8: maxlimit=0.198 minlimit=0.079 preferedwidth=0.198 toplayer_minwidth=0.113 toplayer_maxwidth=0.143 toplayer_prefwidth=0.117 midlayer1_minwidth=0.115 midlayer1_maxwidth=0.115 midlayer1_prefwidth=0.115 midlayer2_minwidth=0.115 midlayer2_maxwidth=0.115 midlayer2_prefwidth=0.115 midlayer3_minwidth=0.198 midlayer4_minwidth=0.198 midlayer5_minwidth=0.115 midlayer5_maxwidth=0.115 midlayer5_prefwidth=0.115 midlayer6_minwidth=0.115 midlayer6_maxwidth=0.115 midlayer6_prefwidth=0.115 midlayer7_maxwidth=0.087 midlayer7_prefwidth=0.087 midlayer8_minwidth=0.115 midlayer8_maxwidth=0.115 midlayer8_prefwidth=0.115 midlayer9_minwidth=0.133 midlayer9_maxwidth=0.133 midlayer9_prefwidth=0.133 midlayer10_minwidth=0.198 midlayer11_minwidth=0.198 midlayer12_minwidth=0.133 midlayer12_maxwidth=0.133 midlayer12_prefwidth=0.133 midlayer13_minwidth=0.115 midlayer13_maxwidth=0.115 midlayer13_prefwidth=0.115 midlayer14_maxwidth=0.087 midlayer14_prefwidth=0.087 bottomlayer_minwidth=0.113 bottomlayer_maxwidth=0.143 bottomlayer_prefwidth=0.117 impedanceprofiledriven=TRUE impedanceprofileid={F22BED46-E16F-4103-815A-6A081543B36A} minimp=50.000000 maximp=50.000000 favimp=50.000000 // Single line impedance 45 Ohm
Width "Single 50" [InNetClass('Single_50')] p9: maxlimit=0.254 minlimit=0.062 preferedwidth=0.254 toplayer_minwidth=0.112 toplayer_maxwidth=0.116 toplayer_prefwidth=0.112 midlayer1_minwidth=0.092 midlayer1_maxwidth=0.092 midlayer1_prefwidth=0.092 midlayer2_minwidth=0.092 midlayer2_maxwidth=0.092 midlayer2_prefwidth=0.092 midlayer5_minwidth=0.092 midlayer5_maxwidth=0.092 midlayer5_prefwidth=0.092 midlayer6_minwidth=0.092 midlayer6_maxwidth=0.092 midlayer6_prefwidth=0.092 midlayer7_maxwidth=0.069 midlayer7_prefwidth=0.069 midlayer8_minwidth=0.092 midlayer8_maxwidth=0.092 midlayer8_prefwidth=0.092 midlayer13_minwidth=0.092 midlayer13_maxwidth=0.092 midlayer13_prefwidth=0.092 midlayer14_maxwidth=0.069 midlayer14_prefwidth=0.069 bottomlayer_minwidth=0.112 bottomlayer_maxwidth=0.116 bottomlayer_prefwidth=0.112 impedanceprofiledriven=TRUE impedanceprofileid={C52096D4-C36E-4BDB-BB83-9E54FFDADA41} minimp=50.000000 maximp=50.000000 favimp=50.000000 checkconnectedcopper=TRUE // Single impedance line 50 Ohm
Width [InNetClass('SFP_diff')] p10 off: maxlimit=0.254 minlimit=0.254 preferedwidth=0.254
22 further rules are at their usual default settings.

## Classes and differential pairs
component class GND: J31
component class I2C_Bridge_2: C303_I2C_Bridge_2 R3_I2C_Bridge_2 R4_I2C_Bridge_2 R5_I2C_Bridge_2 R6_I2C_Bridge_2 R7_I2C_Bridge_2 R8_I2C_Bridge_2 R9_I2C_Bridge_2 R10_I2C_Bridge_2 R223_I2C_Bridge_2 R224_I2C_Bridge_2 R225_I2C_Bridge_2 R226_I2C_Bridge_2 R227_I2C_Bridge_2 R558_I2C_Bridge_2 R559_I2C_Bridge_2 R560_I2C_Bridge_2 TP1_I2C_Bridge_2 TP2_I2C_Bridge_2 TP3_I2C_Bridge_2 TP4_I2C_Bridge_2 TP5_I2C_Bridge_2 TP6_I2C_Bridge_2 TP7_I2C_Bridge_2 TP8_I2C_Bridge_2 TP9_I2C_Bridge_2 TP10_I2C_Bridge_2 TP11_I2C_Bridge_2 TP12_I2C_Bridge_2 TP13_I2C_Bridge_2 TP14_I2C_Bridge_2 TP15_I2C_Bridge_2 TP16_I2C_Bridge_2 TP17_I2C_Bridge_2 TP18_I2C_Bridge_2 U3_I2C_Bridge_2
component class I2C_Expander_16: C311_I2C_Expander_16 U35_I2C_Expander_16
component class I2C_Expander_15: C311_I2C_Expander_15 U35_I2C_Expander_15
component class I2C_Expander_14: C311_I2C_Expander_14 U35_I2C_Expander_14
component class I2C_Expander_13: C311_I2C_Expander_13 U35_I2C_Expander_13
component class I2C_Expander_12: C311_I2C_Expander_12 U35_I2C_Expander_12
component class I2C_Expander_11: C311_I2C_Expander_11 U35_I2C_Expander_11
component class I2C_Expander_10: C311_I2C_Expander_10 U35_I2C_Expander_10
component class I2C_Expander?: C311_I2C_Expander? U35_I2C_Expander?
net class Power_Line_40A: 0.85V@40A_INA US+_Vcc_PS_IntFp
net class Power_Line_20A: 3V3_Rail RAM_Vcc1V2 Vout1_1 Vout2_1
net class Power_Line_10A: 3.3Vaux 5V_RAIL 12V_HiSpeed Vout1_2 Vout_5V@10A_INA
net class Power_Line_2A: 0V9@1A_REG3 0V85@2A 1V0@1.5A 1V8@0.5A_ADC_filtered 1V8@1.5A 2V5@1.5A 3.3V_LN_1 3.3V_Stable_1 3.3V_Stable_2 3.3V_Stable_3 3V3_Rail 12V_PCIE0 12V_PCIE0_CM 12V_PCIE1 12V_PCIE1_CM 12V_PCIE2 12V_PCIE2_CM 12V_PCIE3 12V_PCIE3_CM 12V_PCIE4 12V_PCIE4_CM FTDI_5V FTDI_VBUS FTDI_VccIO NetC568_2 NetC674_2
component class I2C_Expander1: C311_I2C_Expander1 U35_I2C_Expander1
component class U_FPGA_Decoupling: C738 C739 C740 C741 C742 C743 C744 C745 C746 C747 C748 C749 C750 C751 C752 C753 C754 C755 C756 C757 C758 C759 C760 C761 C762 C763 C764 C765
component class U_Expander_RESET: R746 R747 R748 R749 R750 R751 R752 R753 R754 R755 R756 R757 R758 R759 R760 R761 R762 R763
net class NVME_DATA_BANK: NVME_C_RX_1_N NVME_C_RX_1_P NVME_C_RX_O_N NVME_C_RX_O_P NVME_C_TX_1_N NVME_C_TX_1_P NVME_C_TX_O_N NVME_C_TX_O_P
component class U_ST1L08_5V_0V6: C720 C721 C722 C723 R689 R690 R691 U73
component class U_Pomiar_napiecia_high_curr: C310 R617 U72
component class U_UM78M_12_8V: C713 C714 U71
component class U_TPS7A88_3V3_1V8_0V9V@2x1A: C705 C706 C707 C708 C709 C710 C711 C712 R671 R672 R673 R674 R676 R745 U70
component class U_ADP1741_3V3_0V85: C674 C675 C676 C719 FB45 R435 R644 R645 R646 R668 U69
net class eMMC_Data: eMMC_data0 eMMC_data1 eMMC_data2 eMMC_data3 eMMC_data4 eMMC_data5 eMMC_data6 eMMC_data7
net class eMMC_Cmd: eMMC_clk eMMC_cmd eMMC_rst
component class Debug: C558 C559 C560 C658 C659 C660 C661 C662 C663 C664 C665 C666 C667 C668 C669 C670 C671 C672 C673 C791 C792 D15 FB31 FB32 FB43 FB44 P12 R401 R402 R403 R404 R405 R406 R407 R408 R409 R410 R411 R412 R413 R414 R415 R416 R417 R418 R419 R420 R421 R422 R423 R424 R635 R636 R637 R638 R639 R640 R641 R642 R643 R721 R722 R723 R724 R725 R726 R727 R728 R729 R730 R731 R732 R733 R734 U53 U54 U55 U56 U57 U77 U78 U79 X8
component class LowCurr: C304 C305 C306 C307 C308 C354 C355 C603 C604 C605 C606 C607 C610 C611 C612 C613 C614 C615 C616 C617 C618 C619 C620 C621 C622 C623 C624 C625 C626 D16 D17 D18 D19 L13 L15 L16 L17 L18 R113 R114 R212 R214 R216 R218 R220 R274 R284 R305 R308 R309 U19 U67
net class uSD_to_MIO: CD_H DIR_CMD DIR_DAT0_H DIR_DAT1_H uSD_CLK uSD_CMD uSD_D0 uSD_D1 uSD_D2 uSD_D3 uSD_D4
net class uSD_to_Driv: CD_H CMD_SD DATA0_SD DATA1_SD DATA2_SD DATA3_SD SD_Card_CLK
component class U_Detektor_otwarcia: BT1 BT? C609 C678 C679 C680 D20 D21 D22 D23 R647 R648 R649 R650 R651 R652 R653 R654 R655 R656 R657 R658 T22 T23 T24 T25 T26 T27 T28 T29 T30 T31
net class RAM_DQS_Strobe: DDR4_DQS_0_N DDR4_DQS_0_P DDR4_DQS_1_N DDR4_DQS_1_P DDR4_DQS_2_N DDR4_DQS_2_P DDR4_DQS_3_N DDR4_DQS_3_P DDR4_DQS_4_N DDR4_DQS_4_P DDR4_DQS_5_N DDR4_DQS_5_P DDR4_DQS_6_N DDR4_DQS_6_P DDR4_DQS_7_N DDR4_DQS_7_P DDR4_DQS_8_N DDR4_DQS_8_P
net class RAM_Data_IO: DDR4_DM0 DDR4_DM1 DDR4_DM2 DDR4_DM3 DDR4_DM4 DDR4_DM5 DDR4_DM6 DDR4_DM7 DDR4_DQ0 DDR4_DQ1 DDR4_DQ2 DDR4_DQ3 DDR4_DQ4 DDR4_DQ5 DDR4_DQ6 DDR4_DQ7 DDR4_DQ8 DDR4_DQ9 DDR4_DQ10 DDR4_DQ11 DDR4_DQ12 DDR4_DQ13 DDR4_DQ14 DDR4_DQ15 DDR4_DQ16 DDR4_DQ17 DDR4_DQ18 DDR4_DQ19 DDR4_DQ20 DDR4_DQ21 DDR4_DQ22 DDR4_DQ23 DDR4_DQ24 DDR4_DQ25 DDR4_DQ26 DDR4_DQ27 DDR4_DQ28 DDR4_DQ29 DDR4_DQ30 DDR4_DQ31 DDR4_DQ32 DDR4_DQ33 DDR4_DQ34 DDR4_DQ35 DDR4_DQ36 DDR4_DQ37 DDR4_DQ38 DDR4_DQ39 DDR4_DQ40 DDR4_DQ41 DDR4_DQ42 DDR4_DQ43 DDR4_DQ44 DDR4_DQ45 DDR4_DQ46 DDR4_DQ47 DDR4_DQ48 DDR4_DQ49 DDR4_DQ50 DDR4_DQ51 DDR4_DQ52 DDR4_DQ53 DDR4_DQ54 DDR4_DQ55 DDR4_DQ56 DDR4_DQ57 DDR4_DQ58 DDR4_DQ59 DDR4_DQ60 DDR4_DQ61 DDR4_DQ62 DDR4_DQ63
net class Power_Line_1A: 3.3V_PS_Config 12V_HiSpeed ADP1741_3.6V FPGA_Vcc_HD NetD16_2 NetD17_1 NetD17_2 NetD18_1 NetD18_2 NetD19_1 NetD19_2 Power_3.3_1 Power_3.3_2 US+_Vcc_PS_DDR_504
net class Lenght_DQS_to_Data: DDR4_DM0 DDR4_DM1 DDR4_DM2 DDR4_DM3 DDR4_DM4 DDR4_DM5 DDR4_DM6 DDR4_DM7 DDR4_DQ0 DDR4_DQ1 DDR4_DQ2 DDR4_DQ3 DDR4_DQ4 DDR4_DQ5 DDR4_DQ6 DDR4_DQ7 DDR4_DQ8 DDR4_DQ9 DDR4_DQ10 DDR4_DQ11 DDR4_DQ12 DDR4_DQ13 DDR4_DQ14 DDR4_DQ15 DDR4_DQ16 DDR4_DQ17 DDR4_DQ18 DDR4_DQ19 DDR4_DQ20 DDR4_DQ21 DDR4_DQ22 DDR4_DQ23 DDR4_DQ24 DDR4_DQ25 DDR4_DQ26 DDR4_DQ27 DDR4_DQ28 DDR4_DQ29 DDR4_DQ30 DDR4_DQ31 DDR4_DQ32 DDR4_DQ33 DDR4_DQ34 DDR4_DQ35 DDR4_DQ36 DDR4_DQ37 DDR4_DQ38 DDR4_DQ39 DDR4_DQ40 DDR4_DQ41 DDR4_DQ42 DDR4_DQ43 DDR4_DQ44 DDR4_DQ45 DDR4_DQ46 DDR4_DQ47 DDR4_DQ48 DDR4_DQ49 DDR4_DQ50 DDR4_DQ51 DDR4_DQ52 DDR4_DQ53 DDR4_DQ54 DDR4_DQ55 DDR4_DQ56 DDR4_DQ57 DDR4_DQ58 DDR4_DQ59 DDR4_DQ60 DDR4_DQ61 DDR4_DQ62 DDR4_DQ63
net class Lenght_DQS_to_CK: DDR4_DQS_0_N DDR4_DQS_0_P DDR4_DQS_1_N DDR4_DQS_1_P DDR4_DQS_2_N DDR4_DQS_2_P DDR4_DQS_3_N DDR4_DQS_3_P DDR4_DQS_4_N DDR4_DQS_4_P DDR4_DQS_5_N DDR4_DQS_5_P DDR4_DQS_6_N DDR4_DQS_6_P DDR4_DQS_7_N DDR4_DQS_7_P DDR4_DQS_8_N DDR4_DQS_8_P
net class Lenght_CK_to_Addr: DDR4_CK_N DDR4_CK_P
differential pair class Diff_76_to_90_Ram_CLK: DDR4_CK
net class RAM_Adress: DDR4_A0 DDR4_A1 DDR4_A2 DDR4_A3 DDR4_A4 DDR4_A5 DDR4_A6 DDR4_A7 DDR4_A8 DDR4_A9 DDR4_A10 DDR4_A11 DDR4_A12 DDR4_A13 DDR4_ACT_N DDR4_BA0 DDR4_BA1 DDR4_BG0 DDR4_CAS DDR4_CKE0 DDR4_CS_B DDR4_DQS_ODT0 DDR4_PARITY DDR4_RAM_RST_N DDR4_RAS DDR4_WE
component class U_Power_48_20V@3A: C595 C596 C597 C598 C693 C694 C695 C696 C697 C698 C699 C700 C701 C702 C703 C704 D26 D27 L22 R140 R149 R150 R159 R160 R665 R666 R667 R669 R670 R764 T34 T35 U65
net class WR_CLK_C: WR_Source_CLK_N WR_Source_CLK_P
net class WR_CLK_C_LMK: WR_LMK_CLK_IN_N WR_LMK_CLK_IN_P
net class WR_CLK2: WR_LMK_CLK_HF2_N WR_LMK_CLK_HF2_P
net class WR_CLK1: WR_LMK_CLK_HF1_N WR_LMK_CLK_HF1_P
net class RAIL_CLK: CLK_Fanout_In_N CLK_Fanout_In_P
net class PCIE4_SysRef_FPGA: PCIE4_SysRef_FPGA_N PCIE4_SysRef_FPGA_P
net class PCIE3_SysRef_FPGA: PCIE3_SysRef_FPGA_N PCIE3_SysRef_FPGA_P
net class PCIE2_SysRef_FPGA: PCIE2_SysRef_FPGA_N PCIE2_SysRef_FPGA_P
net class PCIE1_SysRef_FPGA: PCIE1_SysRef_FPGA_N PCIE1_SysRef_FPGA_P
net class PCIE0_Sysref_FPGA: PCIE0_SysRef_FPGA_N PCIE0_SysRef_FPGA_P
component class U_Pomiar_pradu_napiecia_1: C309_U_Pomiar_pradu_napiecia_1 R448_U_Pomiar_pradu_napiecia_1 U64_U_Pomiar_pradu_napiecia_1
component class U_Pomiar_pradu_napiecia_2: C309_U_Pomiar_pradu_napiecia_2 R448_U_Pomiar_pradu_napiecia_2 U64_U_Pomiar_pradu_napiecia_2
component class U_Pomiar_pradu_napiecia_3: C309_U_Pomiar_pradu_napiecia_3 R448_U_Pomiar_pradu_napiecia_3 U64_U_Pomiar_pradu_napiecia_3
component class U_Pomiar_pradu_napiecia_4: C309_U_Pomiar_pradu_napiecia_4 R448_U_Pomiar_pradu_napiecia_4 U64_U_Pomiar_pradu_napiecia_4
net class LTC_6952_3_REF: LTC6952_3_REF_N LTC6952_3_REF_P
net class LTC_6952_3_REF_SMA: LTC6952_3_REF_SMA_N LTC6952_3_REF_SMA_P
net class LTC_6952_2_REF: LTC6952_2_REF_N LTC6952_2_REF_P
net class LTC_6952_2_REF_SMA: LTC6952_2_REF_SMA_N LTC6952_2_REF_SMA_P
net class LTC_6952_1_REF: LTC6952_1_REF_N LTC6952_1_REF_P
net class Bank505_MGTRREFx_: CLK_GTR_T1_N CLK_GTR_T1_P CLK_GTR_T2_N CLK_GTR_T2_P CLK_GTR_T3_N CLK_GTR_T3_P
component class DAC: C320 C321 C322 C323 R481 R608 R609 U30 X2 X3
net class Si53323_2_Q2_LVDS: Si53323_2_Q2_LVDS_N Si53323_2_Q2_LVDS_P
net class Si53323_1_Q2_LVDS: Si53323_1_Q2_LVDS_N Si53323_1_Q2_LVDS_P
net class DATA_ETH_TO_PHY: TD_A_N TD_A_P TD_B_N TD_B_P TD_C_N TD_C_P TD_D_N TD_D_P
component class SFP_Group+IMU: R469 R470 R471 R472 R473 R474 R475 R476 R477 R478 R479 R480
component class HighSpeed: R427 R449 R450 R451 R452 R453 R454 R538
component class CLK_MUX: C324 C325 C326 C327 C328 C329 C330 C333 C336 C337 C338 C339 C340 C341 C342 C343 C344 C724 C725 C726 C727 FB23 FB24 J26 R245 R246 R247 R248 R249 R250 R251 R252 R253 R254 R255 R256 R257 R258 R259 R260 R261 R262 R263 R264 R265 R291 R301 R384 R385 R386 R387 R482 R483 R484 R485 R486 R487 R488 R489 T36 U31 U32 U33
net class Si53323_2_Q2: Si53323_2_Q2_N Si53323_2_Q2_P
net class Si53323_2_Q1: Si53323_2_Q1_N Si53323_2_Q1_P
net class Si53323_2_CLK1: Si53323_2_CLK1_N Si53323_2_CLK1_P
net class Si53323_1_Q2: Si53323_1_Q2_N Si53323_1_Q2_P
net class Si53323_1_Q1: Si53323_1_Q1_N Si53323_1_Q1_P
net class RefClk_Si53323: RefClk_Si53323_N RefClk_Si53323_P
net class MUX_DIV_OUT: OSC_Out_DIV_N OSC_Out_DIV_P
net class MUX_DIV_OUT_I: Osc_in_Si53323_2_N Osc_in_Si53323_2_P
net class CLM_M_OSC_IN_C: OSC_500Out
net class CLK_SMA_2: CLK_SMA2_N CLK_SMA2_P
net class CLK_SMA_1: CLK_SMA1_N CLK_SMA1_P
net class CLK_SMA_0: CLK_SMA0_N CLK_SMA0_P
net class CLK_SMA2_C: CLK_SMA2_C_N CLK_SMA2_C_P
net class CLK_SMA1_C: CLK_SMA1_C_N CLK_SMA1_C_P
net class CLK_SMA0_C: CLK_SMA0_C_N CLK_SMA0_C_P
net class CLK_M_OSC_In: CLK_M_OSC_In
differential pair class Diff_76_to_90_Ram_DQS: DDR4_DQS_0 DDR4_DQS_1 DDR4_DQS_2 DDR4_DQS_3 DDR4_DQS_4 DDR4_DQS_5 DDR4_DQS_6 DDR4_DQS_7 DDR4_DQS_8
net class Single_36_39_50_Adr: DDR4_A0 DDR4_A1 DDR4_A2 DDR4_A3 DDR4_A4 DDR4_A5 DDR4_A6 DDR4_A7 DDR4_A8 DDR4_A9 DDR4_A10 DDR4_A11 DDR4_A12 DDR4_A13 DDR4_ACT_N DDR4_BA0 DDR4_BA1 DDR4_BG0 DDR4_CAS DDR4_CKE0 DDR4_CS_B DDR4_DQS_ODT0 DDR4_PARITY DDR4_RAM_RST_N DDR4_RAS DDR4_WE
net class Diff_76_86_90: DDR4_DQS_0_N DDR4_DQS_0_P DDR4_DQS_1_N DDR4_DQS_1_P DDR4_DQS_2_N DDR4_DQS_2_P DDR4_DQS_3_N DDR4_DQS_3_P DDR4_DQS_4_N DDR4_DQS_4_P DDR4_DQS_5_N DDR4_DQS_5_P DDR4_DQS_6_N DDR4_DQS_6_P DDR4_DQS_7_N DDR4_DQS_7_P DDR4_DQS_8_N DDR4_DQS_8_P
net class RAM_Clock_Signal: DDR4_CK_N DDR4_CK_P
component class U_Pomiar_pradu_napiecia_5: C309_U_Pomiar_pradu_napiecia_5 R448_U_Pomiar_pradu_napiecia_5 U64_U_Pomiar_pradu_napiecia_5
component class U_Pomiar_pradu_napiecia_6: C309_U_Pomiar_pradu_napiecia_6 R448_U_Pomiar_pradu_napiecia_6 U64_U_Pomiar_pradu_napiecia_6
component class U_Pomiar_pradu_napiecia_7: C309_U_Pomiar_pradu_napiecia_7 R448_U_Pomiar_pradu_napiecia_7 U64_U_Pomiar_pradu_napiecia_7
component class U_Pomiar_pradu_napiecia_8: C309_U_Pomiar_pradu_napiecia_8 R448_U_Pomiar_pradu_napiecia_8 U64_U_Pomiar_pradu_napiecia_8
component class U_Pomiar_pradu_napiecia_9: C309_U_Pomiar_pradu_napiecia_9 R448_U_Pomiar_pradu_napiecia_9 U64_U_Pomiar_pradu_napiecia_9
component class U_5V_to_3V31: C563_U_5V_to_3V31 C564_U_5V_to_3V31 C565_U_5V_to_3V31 C566_U_5V_to_3V31 C567_U_5V_to_3V31 R430_U_5V_to_3V31 R431_U_5V_to_3V31 R432_U_5V_to_3V31 U59_U_5V_to_3V31
channel class Pomiar_pradu_napiecia: U_Pomiar_pradu_napiecia_10 U_Pomiar_pradu_napiecia_11
net class Single_39_50_D: DDR4_DM0 DDR4_DM1 DDR4_DM2 DDR4_DM3 DDR4_DM4 DDR4_DM5 DDR4_DM6 DDR4_DM7 DDR4_DQ0 DDR4_DQ1 DDR4_DQ2 DDR4_DQ3 DDR4_DQ4 DDR4_DQ5 DDR4_DQ6 DDR4_DQ7 DDR4_DQ8 DDR4_DQ9 DDR4_DQ10 DDR4_DQ11 DDR4_DQ12 DDR4_DQ13 DDR4_DQ14 DDR4_DQ15 DDR4_DQ16 DDR4_DQ17 DDR4_DQ18 DDR4_DQ19 DDR4_DQ20 DDR4_DQ21 DDR4_DQ22 DDR4_DQ23 DDR4_DQ24 DDR4_DQ25 DDR4_DQ26 DDR4_DQ27 DDR4_DQ28 DDR4_DQ29 DDR4_DQ30 DDR4_DQ31 DDR4_DQ32 DDR4_DQ33 DDR4_DQ34 DDR4_DQ35 DDR4_DQ36 DDR4_DQ37 DDR4_DQ38 DDR4_DQ39 DDR4_DQ40 DDR4_DQ41 DDR4_DQ42 DDR4_DQ43 DDR4_DQ44 DDR4_DQ45 DDR4_DQ46 DDR4_DQ47 DDR4_DQ48 DDR4_DQ49 DDR4_DQ50 DDR4_DQ51 DDR4_DQ52 DDR4_DQ53 DDR4_DQ54 DDR4_DQ55 DDR4_DQ56 DDR4_DQ57 DDR4_DQ58 DDR4_DQ59 DDR4_DQ60 DDR4_DQ61 DDR4_DQ62 DDR4_DQ63
component class "Xilinx FPGA": R124 R363 R364 R365 R395 R398 R506 R507 R514 R515 R522 R523 R530 R531 R546 R547 R548 R549 R550 R551 R552 R553 R554 R555 R556 R557 R607 R618 R659 R660 R661 R662 R663 R664 R688 R735 R736 R744 R765 R766 R767 R817 R818 R819 R820 R821 R822 R823 R824 TP43 TP44 TP45 TP46 TP47 TP48 TP49 U15
component class U_Pomiar_pradu_napiecia_10: C309_U_Pomiar_pradu_napiecia_10 R448_U_Pomiar_pradu_napiecia_10 U64_U_Pomiar_pradu_napiecia_10
component class U_Pomiar_pradu_napiecia_11: C309_U_Pomiar_pradu_napiecia_11 R448_U_Pomiar_pradu_napiecia_11 U64_U_Pomiar_pradu_napiecia_11
component class PowerDistribition: P7 P8 P9 P10 P11 R229 R230 R455 R456 R457 R458 R459 R460 R461 R462 R463 R464 R465 R466 R467 R468 R593 R594 R595 R596 R597 R598 TP91 TP92
net class USB3._to_C: USB_RX_C_N USB_RX_C_P USB_TX_C_N USB_TX_C_P
net class USB3._C_to_FPGA: USB_RX_N USB_RX_P USB_TX_N USB_TX_P
net class Single_50: CLK_Fanout_In_N CLK_Fanout_In_P CLK_GTR_T1_N CLK_GTR_T1_P CLK_GTR_T2_N CLK_GTR_T2_P CLK_GTR_T3_N CLK_GTR_T3_P CLK_Hi_Rail1_N CLK_Hi_Rail1_P CLK_Hi_Rail1_SysRef_N CLK_Hi_Rail1_SysRef_P CLK_Hi_Rail2_N CLK_Hi_Rail2_P CLK_Hi_Rail2_SysRef_N CLK_Hi_Rail2_SysRef_P CLK_M_OSC_In CLK_NVME_Conn_N CLK_NVME_Conn_P CLK_Q223_T1_N CLK_Q223_T1_P CLK_Q224_T1_N CLK_Q224_T1_P CLK_Q225_T1_N CLK_Q225_T1_P CLK_Q226_T1_N CLK_Q226_T1_P CLK_SMA0_C_N CLK_SMA0_C_P CLK_SMA0_N CLK_SMA0_P CLK_SMA1_C_N CLK_SMA1_C_P CLK_SMA1_N CLK_SMA1_P CLK_SMA2_C_N CLK_SMA2_C_P CLK_SMA2_N CLK_SMA2_P LTC6952_1_REF_N LTC6952_1_REF_P LTC6952_1_VCO_N LTC6952_1_VCO_P LTC6952_2_REF_N LTC6952_2_REF_P LTC6952_2_REF_SMA_N LTC6952_2_REF_SMA_P LTC6952_3_REF_N LTC6952_3_REF_P LTC6952_3_REF_SMA_N LTC6952_3_REF_SMA_P NetC334_1 NetC335_2 NetC341_1 NetC588_1 NetC588_2 NetR543_1 NVME_C_RX_1_N NVME_C_RX_1_P NVME_C_RX_O_N NVME_C_RX_O_P NVME_C_TX_1_N NVME_C_TX_1_P NVME_C_TX_O_N NVME_C_TX_O_P NVMe_Rx_0_N NVMe_Rx_0_P NVMe_Rx_1_N NVMe_Rx_1_P NVMe_Tx_0_N NVMe_Tx_0_P NVMe_Tx_1_N NVMe_Tx_1_P OSC_500Out Osc_in_Si53323_2_N Osc_in_Si53323_2_P OSC_Out_DIV_N OSC_Out_DIV_P PCIE0_SysRef_FPGA_N PCIE0_SysRef_FPGA_P PCIE1_SysRef_FPGA_N PCIE1_SysRef_FPGA_P PCIE2_SysRef_FPGA_N PCIE2_SysRef_FPGA_P PCIE3_SysRef_FPGA_N PCIE3_SysRef_FPGA_P PCIE4_SysRef_FPGA_N PCIE4_SysRef_FPGA_P RefClk_Si53323_N RefClk_Si53323_P SGMI_C_Rx_N SGMI_C_Rx_P SGMI_C_Tx_N SGMI_C_Tx_P SGMI_Rx_N SGMI_Rx_P SGMI_Tx_N SGMI_Tx_P Si53323_1_Q1_N Si53323_1_Q1_P Si53323_1_Q2_LVDS_N Si53323_1_Q2_LVDS_P Si53323_1_Q2_N Si53323_1_Q2_P Si53323_2_CLK1_N Si53323_2_CLK1_P Si53323_2_Q1_N Si53323_2_Q1_P Si53323_2_Q2_LVDS_N Si53323_2_Q2_LVDS_P Si53323_2_Q2_N Si53323_2_Q2_P TD_A_N TD_A_P TD_B_N TD_B_P TD_C_N TD_C_P TD_D_N TD_D_P WR_LMK_CLK_HF1_N WR_LMK_CLK_HF1_P WR_LMK_CLK_HF2_N WR_LMK_CLK_HF2_P WR_LMK_CLK_IN_N WR_LMK_CLK_IN_P WR_Source_CLK_N WR_Source_CLK_P XO_LMK05028_P
net class Singe_50: Bank505_MGTRREF0_C_N Bank505_MGTRREF0_C_P Bank505_MGTRREF2_C_N Bank505_MGTRREF2_C_P Bank505_MGTRREF3_C_N Bank505_MGTRREF3_C_P NetU2_L25 NetU2_L26
net class NVMe_REFCLK: CLK_NVME_Conn_N CLK_NVME_Conn_P
net class NVMe_DATA: NVMe_Rx_0_N NVMe_Rx_0_P NVMe_Rx_1_N NVMe_Rx_1_P NVMe_Tx_0_N NVMe_Tx_0_P NVMe_Tx_1_N NVMe_Tx_1_P
net class Bank505_MGTRREFx_C: Bank505_MGTRREF0_C_N Bank505_MGTRREF0_C_P Bank505_MGTRREF2_C_N Bank505_MGTRREF2_C_P Bank505_MGTRREF3_C_N Bank505_MGTRREF3_C_P NetU2_L25 NetU2_L26
net class Bank226_MGTREFx_to_C: CLK_Q226_T1_N CLK_Q226_T1_P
